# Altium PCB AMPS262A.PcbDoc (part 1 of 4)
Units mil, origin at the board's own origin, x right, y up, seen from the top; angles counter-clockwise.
Board outline 5314.96 x 4803.15 mil, 4 copper layers (Top Layer, GND, Copper Layer 3, Bottom Layer), stack 79.28 mil thick; 324 components, 156 nets, 943 pads, 1411 vias.
Unrouted connection lines stored in the file: 130.
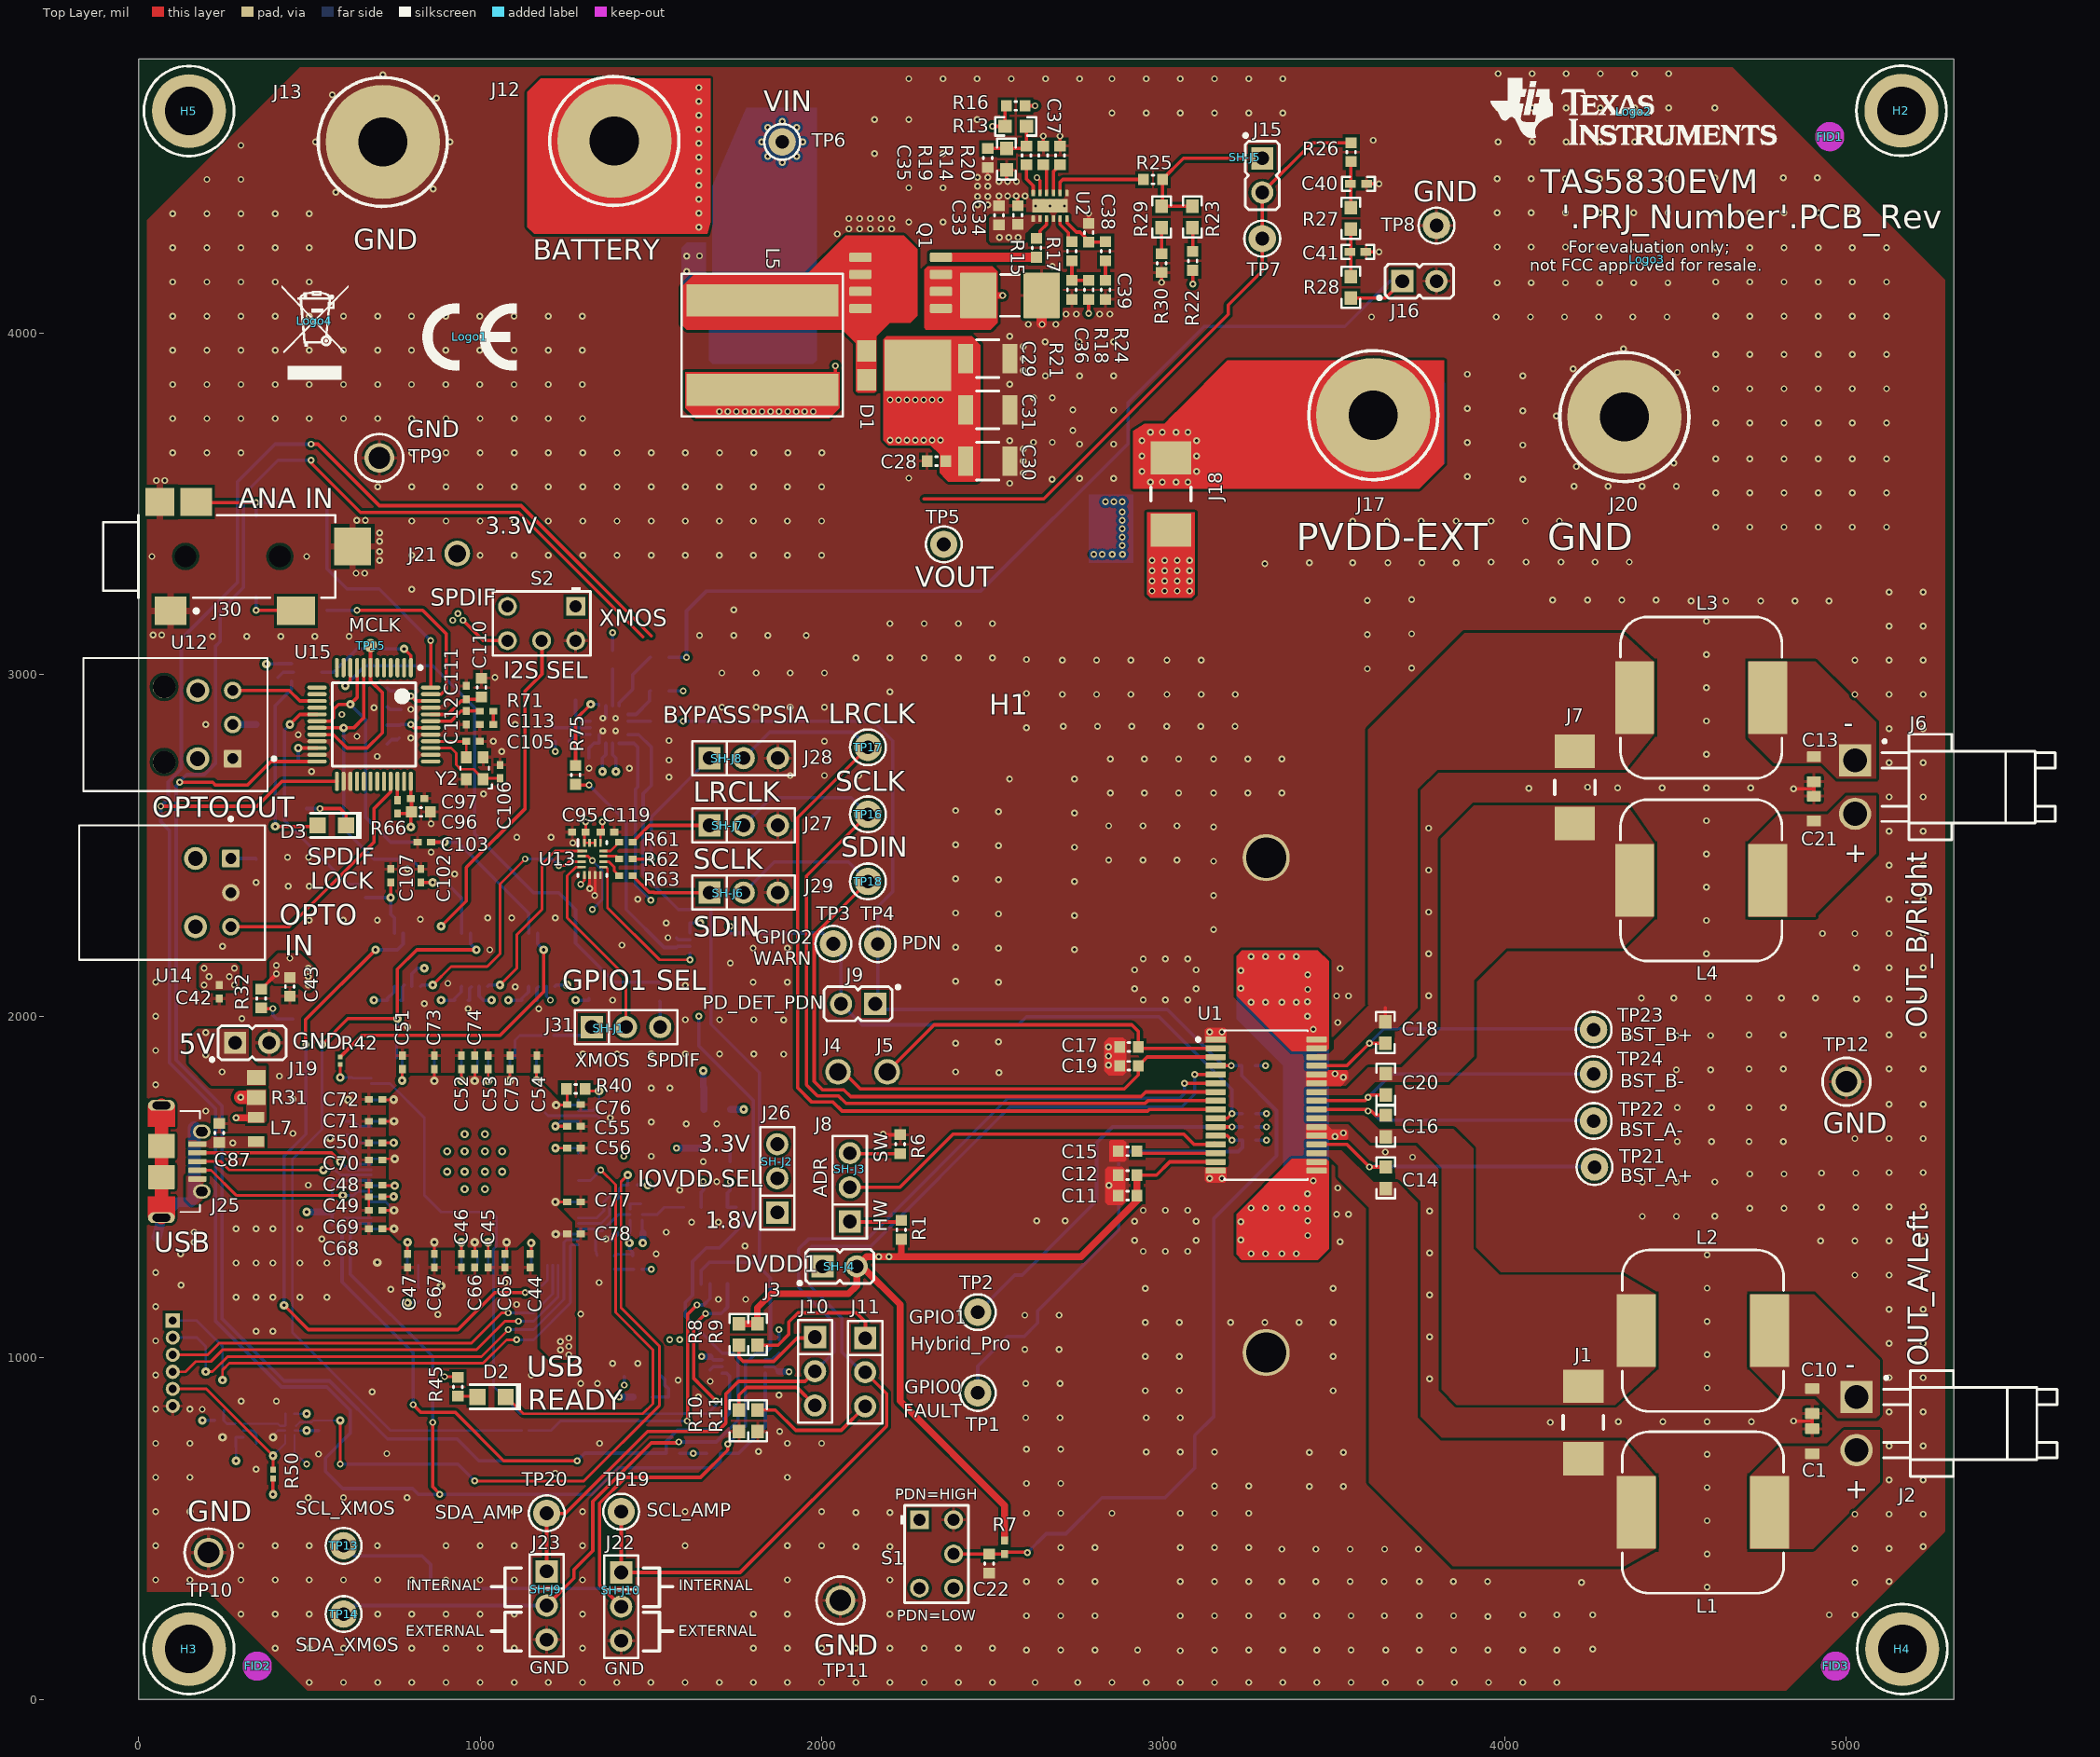
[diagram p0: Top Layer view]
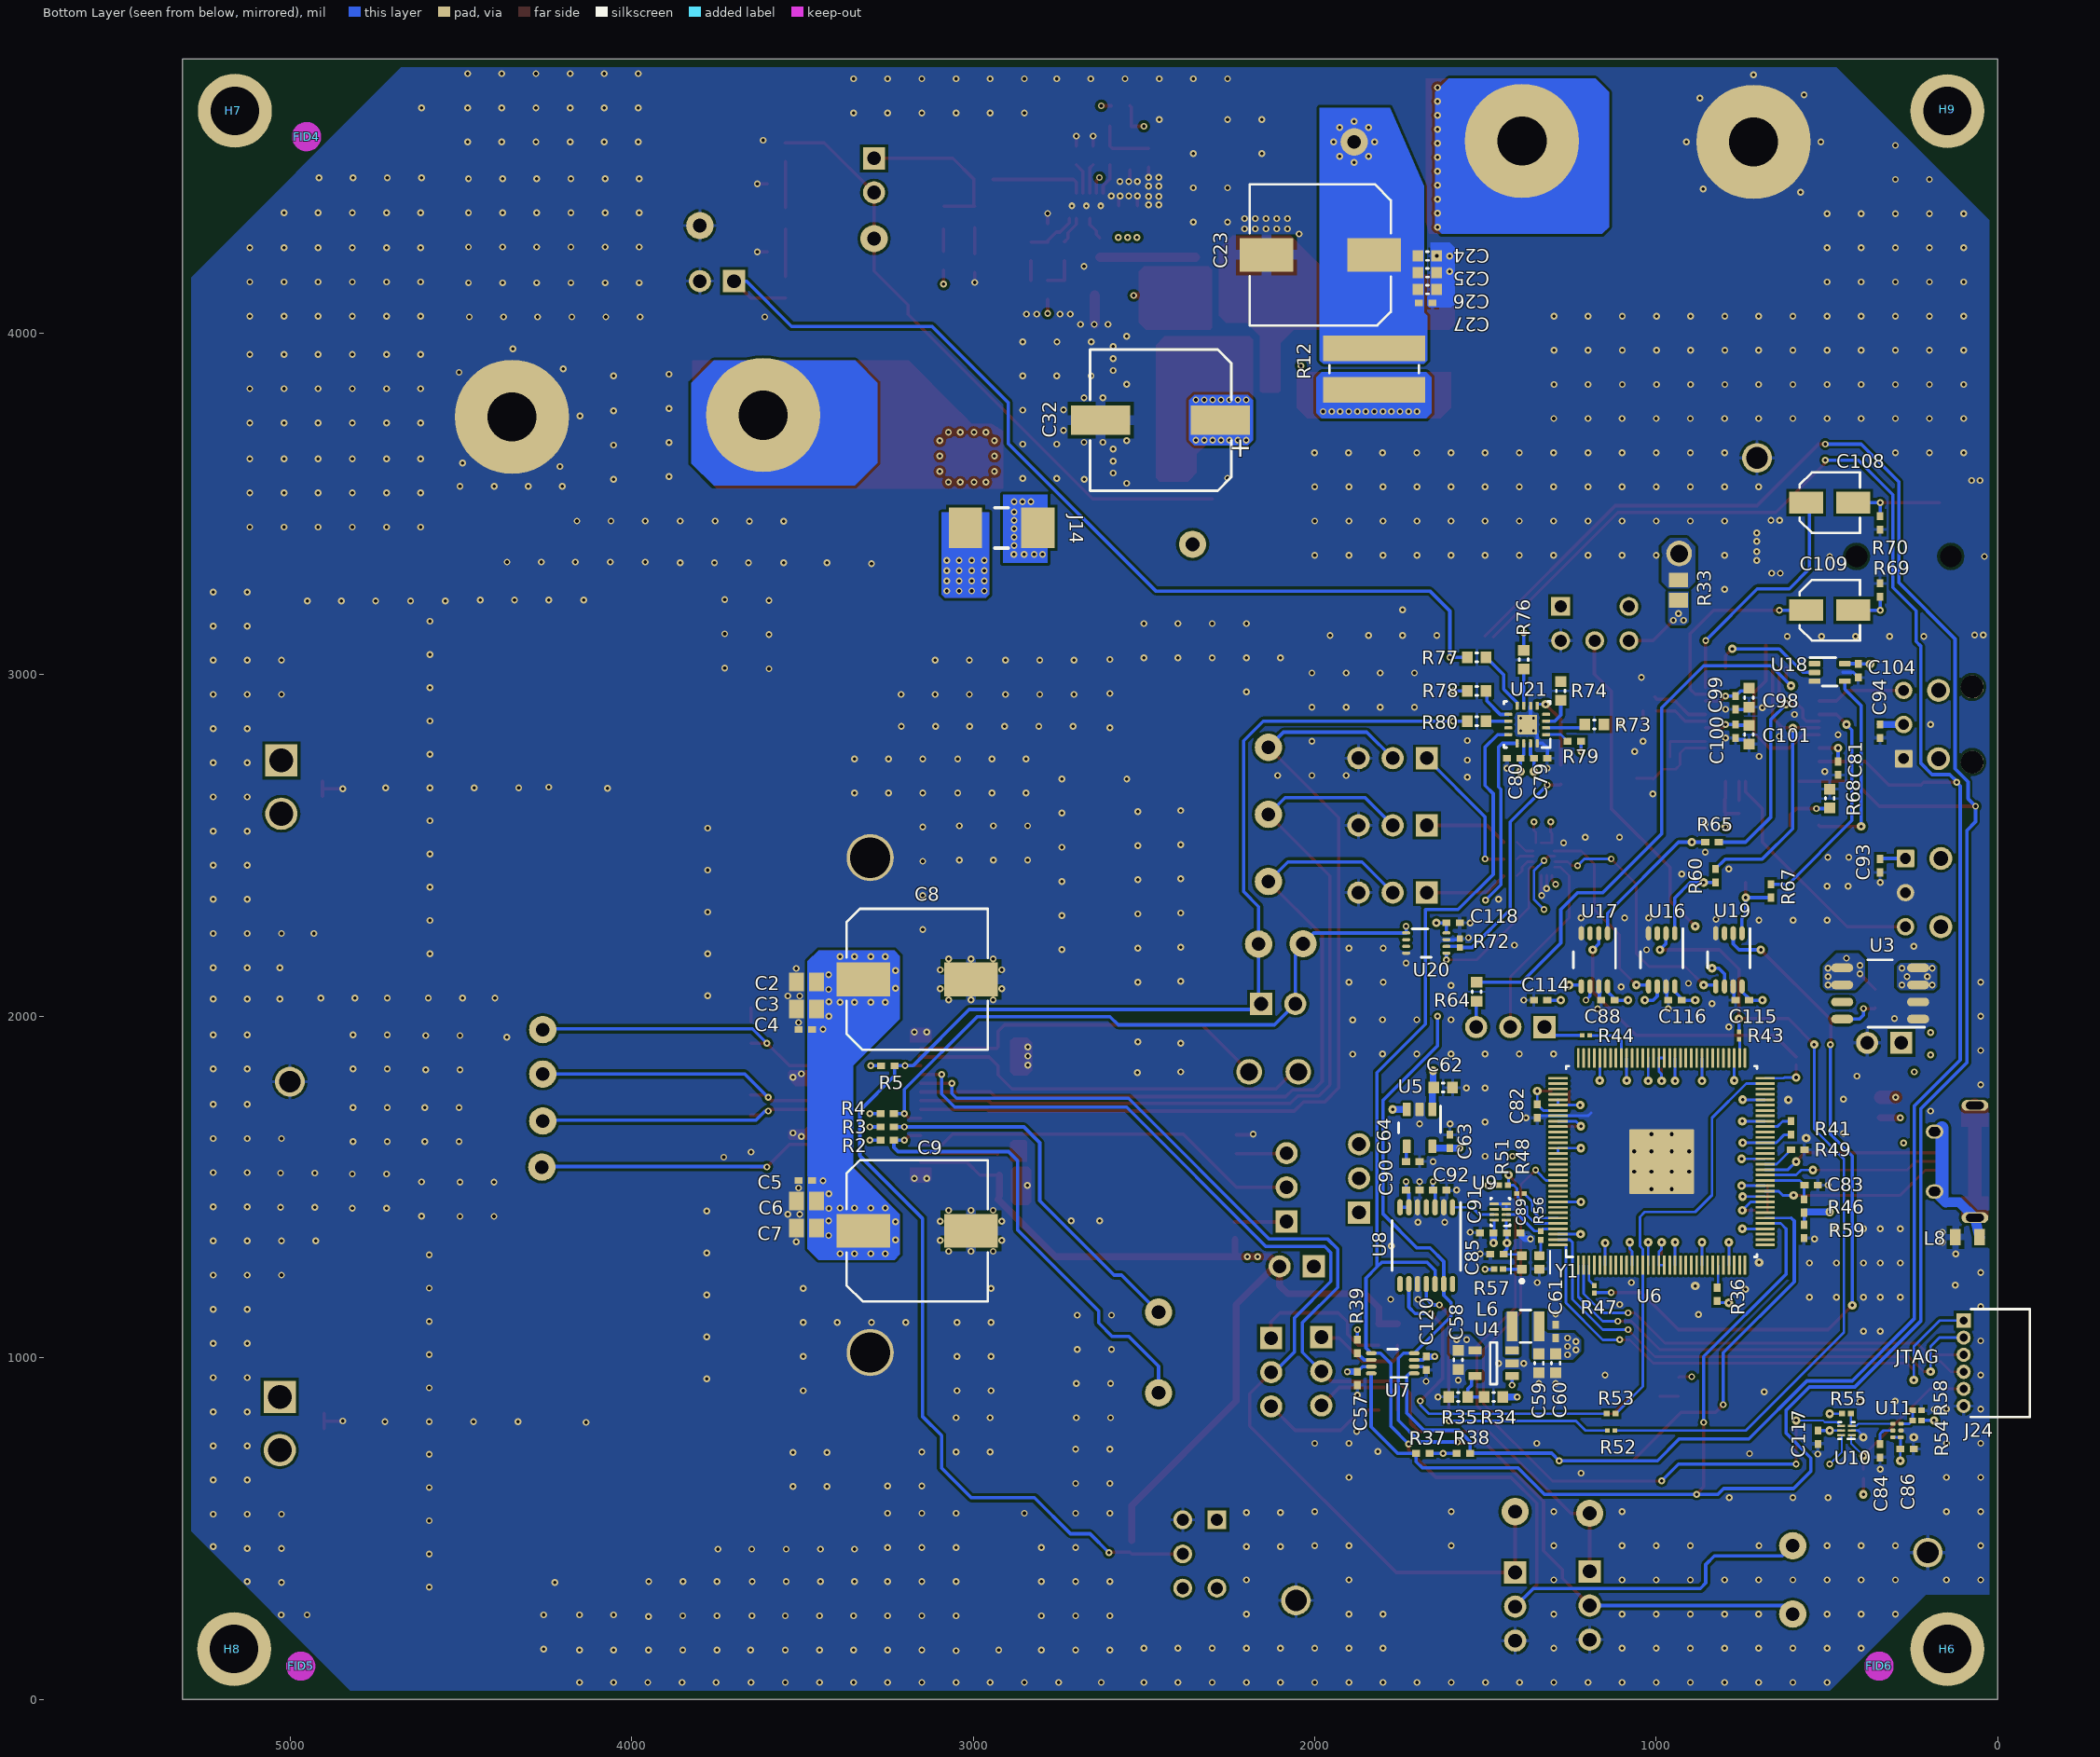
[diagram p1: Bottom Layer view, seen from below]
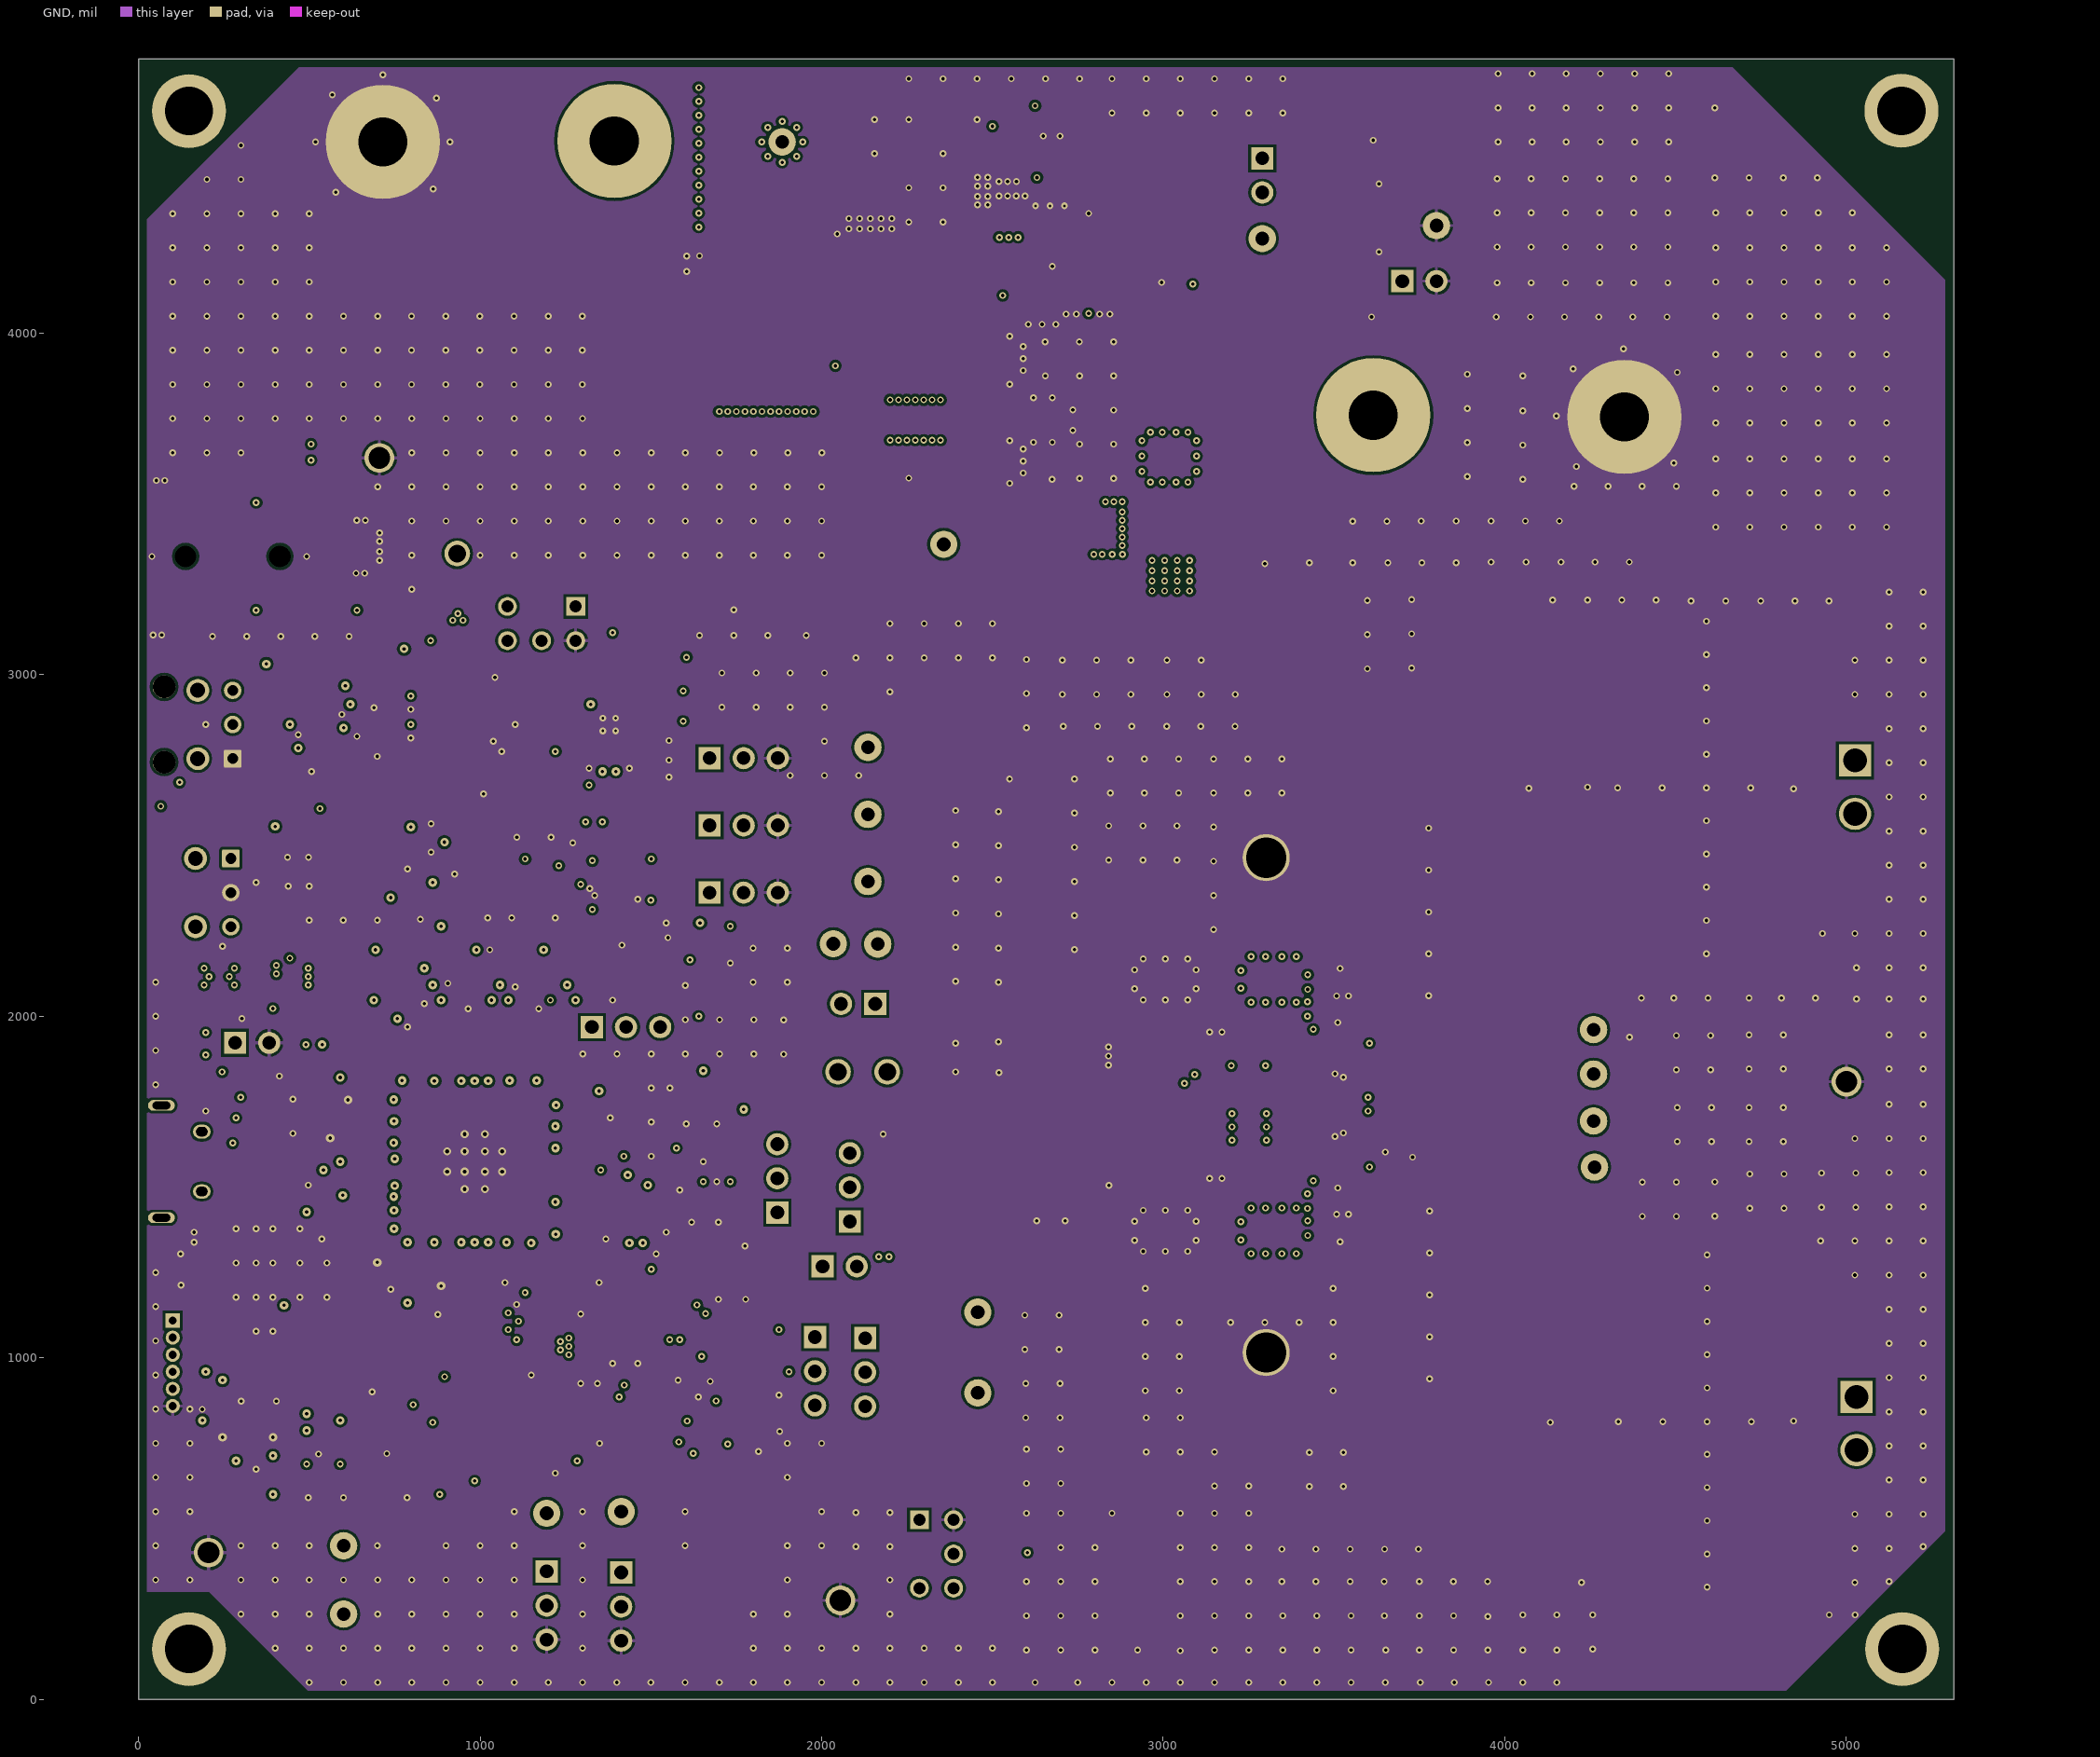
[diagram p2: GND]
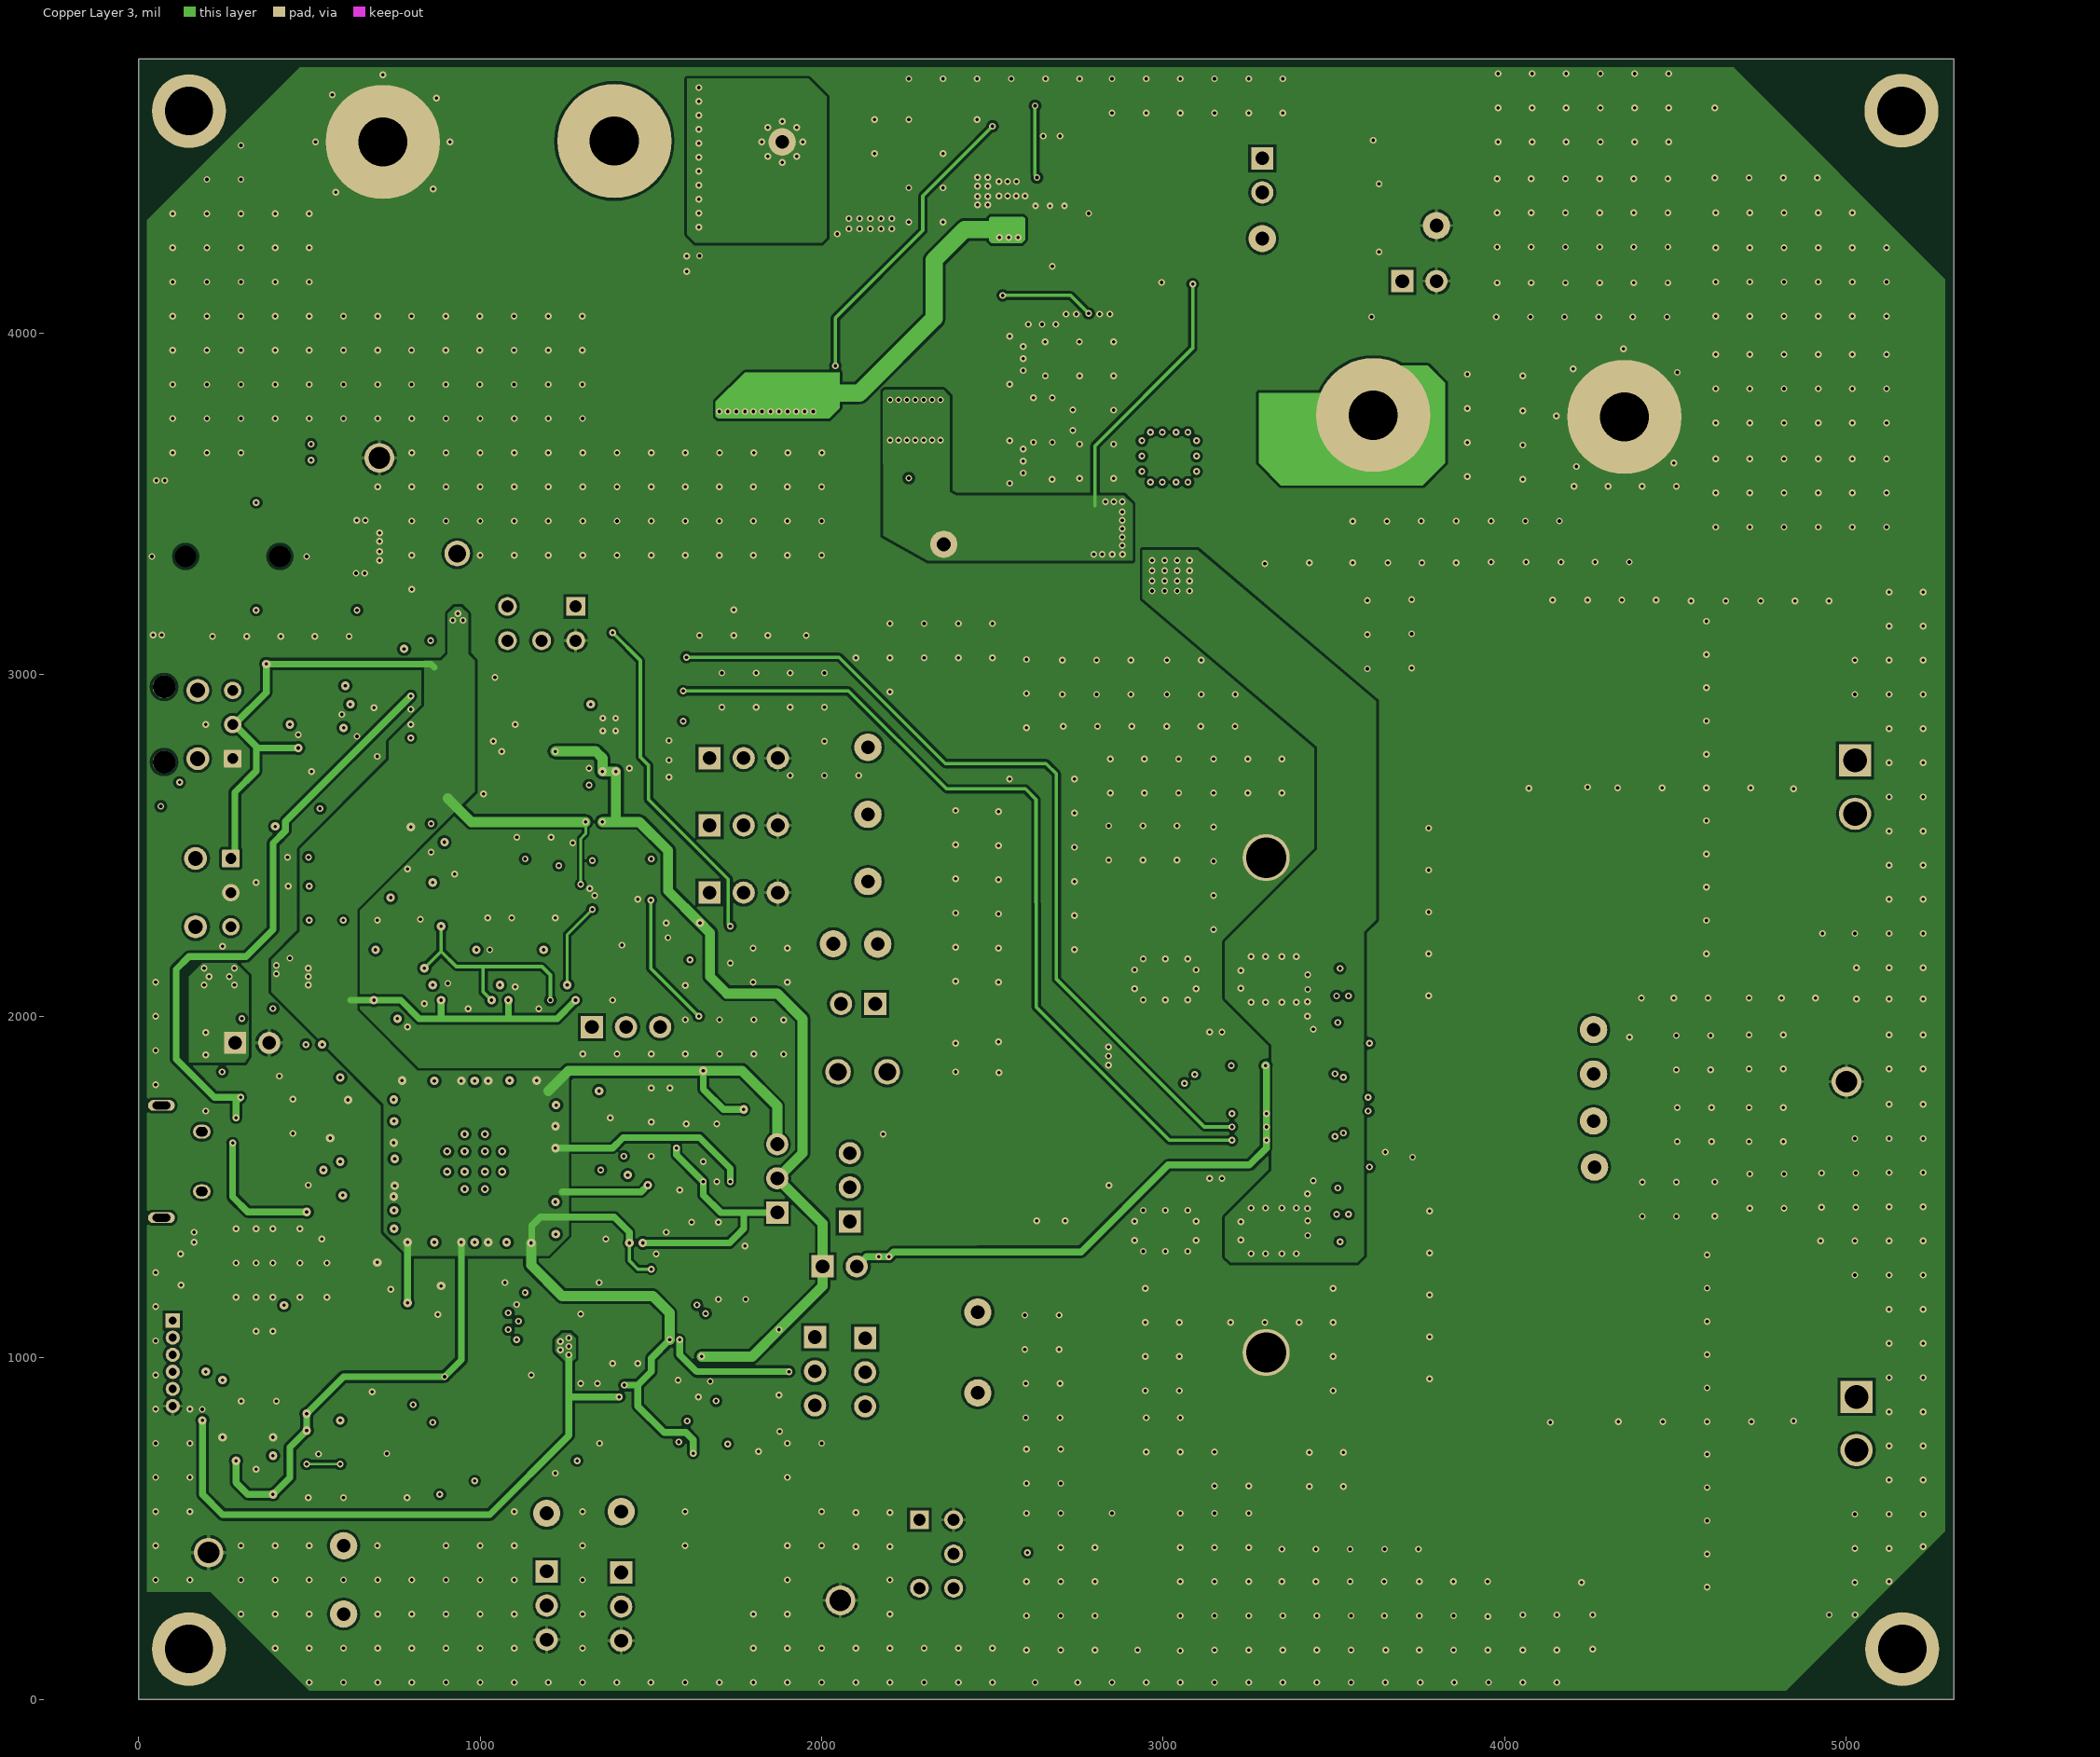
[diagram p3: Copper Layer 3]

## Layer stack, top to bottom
Top Solder: solder mask 0.4, Solder Resist, Dk 3.5
Top Layer: signal copper 2.74
Dielectric 1: prepreg 25, FR-4, Dk 4.2
GND: signal copper 1.4
Dielectric1: core 21, FR-4, Dk 4.2
Copper Layer 3: signal copper 1.4
Dielectric 3: prepreg 25, FR-4, Dk 4.2
Bottom Layer: signal copper 2.74
Bottom Solder: solder mask 0.4, Solder Resist, Dk 3.5

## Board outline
0,0 0,4803.15 5314.96,4803.15 5314.96,0

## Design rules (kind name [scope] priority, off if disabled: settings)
AcuteAngle [All] p1: minimum=4.50000000000000E+0001 checktracksonly=FALSE
AssemblyTestPointUsage [All] p1: valid=2
BoardOutlineClearance BoardOutlineClearance_MountingHoles [OnCopper and InComponentClass('Mounting Holes')] p1: gap=39.37 ignorepadtopadclearanceinfootprint=FALSE
BoardOutlineClearance BoardOutlineClearance_Poly [OnCopper and IsPoly] p2: gap=25 ignorepadtopadclearanceinfootprint=FALSE
BoardOutlineClearance BoardOutlineClearance_CONN_USB_DX4R205JJA [(OnCopper AND (HasFootprint('CONN_USB_DX4R205JJA') OR HasFootprint('SWITCHCRAFT_35RASM'))) and Not InComponentClass('Logo') and not InComponentClass('FiducialMark') and not InRegion(1000,500,4000,800) and not InPoly] p3: gap=75 ignorepadtopadclearanceinfootprint=FALSE except(15: SMDPad-OutlineEdge THPad-OutlineEdge; 29: Via-OutlineEdge)
BoardOutlineClearance [OnCopper and Not InComponentClass('Logo') and not InComponentClass('FiducialMark') and not InRegion(1000,500,4000,800) and not InPoly] p4: gap=75 ignorepadtopadclearanceinfootprint=FALSE except(20: Track-OutlineEdge; 25: Poly-OutlineEdge Poly-CavityEdge Poly-CutoutEdge Poly-SplitBarrior Poly-SplitContinuation Region-OutlineEdge Region-CavityEdge Region-CutoutEdge Region-SplitBarrior Region-SplitContinuation; 29: Via-OutlineEdge; 35: SMDPad-OutlineEdge; 39.37: THPad-OutlineEdge)
Clearance Clearance_FiducialMark [IsKeepOut and InComponentClass('FiducialMark') vs IsPad and InComponentClass('FiducialMark')] p1: gap=0 ignorepadtopadclearanceinfootprint=FALSE
Clearance Clearance_Keepouts [((IsTrack Or IsArc) And Not InPoly) And IsFree and IsKeepOut vs ((IsTrack Or IsArc) And Not InPoly) And IsFree and IsKeepOut] p2: gap=0 ignorepadtopadclearanceinfootprint=FALSE
Clearance Clearance_Poly [InPolygon] p3: gap=7.87 ignorepadtopadclearanceinfootprint=TRUE
Clearance "FootPrint Lib Error" [HasFootprint('DSF*')] p4: gap=7 ignorepadtopadclearanceinfootprint=TRUE except(0: Arc-Hole Track-Hole SMDPad-Hole THPad-Hole Via-Hole Fill-Hole Poly-Hole Region-Hole Text-Hole)
Clearance [All] p5: gap=7.87 ignorepadtopadclearanceinfootprint=TRUE except(0: Arc-Hole Track-Hole SMDPad-Hole THPad-Hole Via-Hole Fill-Hole Poly-Hole Region-Hole Text-Hole)
ComponentClearance ComponentClearance_MOUNTINGHOLE [HasFootprint('APM_RM3X8MM 2701') vs HasFootprint('Keystone_24434')] p1 off: gap=0 collisioncheckmode=3 verticalgap=0 showdistances=FALSE
ComponentClearance ComponentClearance_HEATSINK [InComponent('H1') vs InComponent('U1')] p2 off: gap=0 collisioncheckmode=3 verticalgap=0 showdistances=FALSE
ComponentClearance ComponentClearance_MountingHoles_FiducialMarks [InComponentClass('Mounting Holes') vs InComponentClass('FiducialMark')] p3 off: gap=50 collisioncheckmode=3 verticalgap=10 showdistances=FALSE
ComponentClearance ComponentClearance_Shunt [InComponentClass('Header') vs InComponentClass('Shunt')] p4 off: gap=0 collisioncheckmode=3 verticalgap=0 showdistances=FALSE
ComponentClearance ComponentClearance_Logo [InComponentClass('Logo')] p5 off: gap=50 collisioncheckmode=3 verticalgap=10 showdistances=FALSE
ComponentClearance ComponentClearance_ScrewToNut [(HasFootprint('NY PMS 440 0025 PH')) vs (HasFootprint('Keystone_1902C'))] p6 off: gap=5 collisioncheckmode=3 verticalgap=10 showdistances=FALSE
ComponentClearance ComponentClearance_MountingHoles [InComponentClass('Mounting Holes')] p7 off: gap=250 collisioncheckmode=3 verticalgap=100000 showdistances=FALSE
ComponentClearance ComponentClearance_SmallPassives [HasFootprint('0201*') or HasFootprint('0402*') or HasFootprint('0603*') or HasFootprint('0805*') or HasFootprint('1206*') or HasFootprint('1210*') or HasFootprint('1008*') or HasFootprint('2512*') or HasFootprint('Abracon*') or HasFootprint('DBV*') or HasFootprint('DC*') or HasFootprint('DDA*') or HasFootprint('DEM*') or HasFootprint('DFE*') or HasFootprint('DQM*') or HasFootprint('DRL*') or HasFootprint('DRY*') or HasFootprint('DSF*') or HasFootprint('DSS*') or HasFootprint('FDSD*') or HasFootprint('HAR*') or HasFootprint('HXB*') or HasFootprint('IND*') or HasFootprint('LDC*') or HasFootprint('LTST*') or HasFootprint('MPZ*') or HasFootprint('MRA*') or HasFootprint('NFZ*') or HasFootprint('PG*') or HasFootprint('PW*') or HasFootprint('PT*') or HasFootprint('Relay*') or HasFootprint('RGT*') or HasFootprint('RHB*') or HasFootprint('RLT*') or HasFootprint('RSV*') or HasFootprint('SM*') or HasFootprint('SOT*') or HasFootprint('TP*') or HasFootprint('VLS*') or HasFootprint('XAL*') or HasFootprint('XTAL*') vs HasFootprint('0201*') or HasFootprint('0402*') or HasFootprint('0603*') or HasFootprint('0805*') or HasFootprint('1206*') or HasFootprint('1210*') or HasFootprint('1008*') or HasFootprint('2512*') or HasFootprint('Abracon*') or HasFootprint('DBV*') or HasFootprint('DC*') or HasFootprint('DDA*') or HasFootprint('DEM*') or HasFootprint('DFE*') or HasFootprint('DQM*') or HasFootprint('DRL*') or HasFootprint('DRY*') or HasFootprint('DSF*') or HasFootprint('DSS*') or HasFootprint('FDSD*') or HasFootprint('HAR*') or HasFootprint('HXB*') or HasFootprint('IND*') or HasFootprint('LDC*') or HasFootprint('LTST*') or HasFootprint('MPZ*') or HasFootprint('MRA*') or HasFootprint('NFZ*') or HasFootprint('PG*') or HasFootprint('PW*') or HasFootprint('PT*') or HasFootprint('Relay*') or HasFootprint('RGT*') or HasFootprint('RHB*') or HasFootprint('RLT*') or HasFootprint('RSV*') or HasFootprint('SM*') or HasFootprint('SOT*') or HasFootprint('TP*') or HasFootprint('VLS*') or HasFootprint('XAL*') or HasFootprint('XTAL*')] p8 off: gap=8.5 collisioncheckmode=3 verticalgap=10 showdistances=FALSE
ComponentClearance ComponentClearance_THtoSMT [IsThruComponent vs IsSMTComponent] p9 off: gap=25 collisioncheckmode=3 verticalgap=30 showdistances=FALSE
ComponentClearance ComponentClearance_THtoTH [IsThruComponent vs IsThruComponent] p10 off: gap=30 collisioncheckmode=3 verticalgap=30 showdistances=FALSE
ComponentClearance [All] p11 off: gap=0 collisioncheckmode=3 verticalgap=10 showdistances=FALSE
DiffPairsRouting [All] p1: maxlimit=100 minlimit=10 mostfreqgap=10 toplayer_minwidth=15 toplayer_maxwidth=15 toplayer_prefwidth=15 midlayer1_minwidth=15 midlayer1_maxwidth=15 midlayer1_prefwidth=15 midlayer2_minwidth=15 midlayer2_maxwidth=15 midlayer2_prefwidth=15 bottomlayer_minwidth=15 bottomlayer_maxwidth=15 bottomlayer_prefwidth=15 maxuncoupledlength=1000
FabricationTestPointUsage TestPointUsage [All] p1: valid=2 allowmultiple=FALSE
FabricationTestpoint Testpoint [All] p1: side=3 testpointundercomponent=TRUE minsize=40 maxsize=100 preferedsize=60 minholesize=0 maxholesize=40 preferedholesize=32 testpointgrid=1 allowsidetop=TRUE allowsidebottom=TRUE usegrid=TRUE gridtolerance=0.01
FanoutControl Fanout_LCC [IsLCC] p1: bgadir=Out bgaviamode=Centered fanoutstyle=Auto fanoutdirection=Alternating viagrid=1 // Fanout_LCC (Default Rule)
FanoutControl Fanout_BGA [IsBGA] p2: bgadir=Out bgaviamode=Centered fanoutstyle=Auto fanoutdirection=Alternating viagrid=1 // Fanout_BGA (Default Rule)
FanoutControl Fanout_Default [All] p4: bgadir=Out bgaviamode=Centered fanoutstyle=Auto fanoutdirection=Alternating viagrid=1 // Fanout_Default (Default Rule)
FanoutControl Fanout_Small [(CompPinCount < 5)] p5: bgadir=Out bgaviamode=Centered fanoutstyle=Auto fanoutdirection=OutThenIn viagrid=1 // Fanout_Small (Default Rule)
Height [All] p1 off: minheight=0 maxheight=1050 prefheight=500
HoleSize [All] p1: absolutevalues=TRUE maxlimit=251 minlimit=7.87 maxpercent=80.000 minpercent=20.000
MinimumAnnularRing MinimumAnnularRing_ThermalPadVias [IsVia and InAnyComponent] p1: minimumring=5.91
MinimumAnnularRing [All] p2: minimumring=5
MinimumSolderMaskSliver MinimumSolderMaskSliver_Logo [InComponentClass('Logo') vs InComponentClass('Logo')] p1: minsoldermaskwidth=0.7
MinimumSolderMaskSliver MinimumSolderMaskSliver_DSF [HasFootprint('DSF*')] p2: minsoldermaskwidth=3.5
MinimumSolderMaskSliver [All] p3: minsoldermaskwidth=3.94
NetAntennae [InNet('No Net')] p1: netantennaetolerance=0
PlaneConnect [All] p1: planeconnectstyle=Relief reliefexpansion=10 reliefentries=4 reliefconductorwidth=10 reliefairgap=10
PolygonConnect "Flood VR Bottom Copper Only" [InNet('GND') vs HasFootprint('DDA0008H_N') And OnLayer('Bottom Copper')] p1: connectstyle=Direct reliefconductorwidth=10 reliefentries=4 polygonreliefangle="90 Angle" airgapwidth=10
PolygonConnect "Flood Copper Planes" [InNet('1.0V') or InNet('3.3V') or InNet('GND-PS') or InNet('PVDD') or  InNet('PVDD-VR') or  InNet('VIN') or InNet('3.3V-VR') or  InNet('VIN_3.3V-VR') or InNet('PVDD-3.3V')] p2: connectstyle=Direct reliefconductorwidth=10 reliefentries=4 polygonreliefangle="90 Angle" airgapwidth=10
PolygonConnect "Post Flood GND" [(HasFootprint('DKQ*') or HasFootprint('LDC*') or HasFootprint('MRA*') or HasFootprint('PW*') or HasFootprint('RHB*') or HasFootprint('RLT*') or HasFootprint('TQFP-128')) or InComponentClass('GND Thermals Full Flood') or InComponent('U*') or InComponentClass('GND Full Flood') vs InNet('GND')] p3: connectstyle=Direct reliefconductorwidth=10 reliefentries=4 polygonreliefangle="90 Angle" airgapwidth=10
PolygonConnect "GND Thermals 0.5mm" [InComponentClass('GND Thermals 0.5mm') vs InNet('GND')] p4: connectstyle=Relief reliefconductorwidth=19.68 reliefentries=4 polygonreliefangle="90 Angle" airgapwidth=9.84
PolygonConnect "PVDD Thermals 0.75mm" [InComponentClass('GND Thermals 0.75mm') vs InNet('GND')] p5: connectstyle=Relief reliefconductorwidth=29.53 reliefentries=4 polygonreliefangle="90 Angle" airgapwidth=9.84
PolygonConnect "GND Thermals 0.25mm" [InComponent('C*') or InComponent('J*') or InComponent('L*') or  InComponent('R*') or InComponent('S*') or InComponent('TP*') or  InComponent('Y*') or  InComponent('GND*') vs InNet('GND')] p6: connectstyle=Relief reliefconductorwidth=9.84 reliefentries=4 polygonreliefangle="90 Angle" airgapwidth=7.87
PolygonConnect "Pre Flood" [All] p7: connectstyle=Direct reliefconductorwidth=10 reliefentries=4 polygonreliefangle="90 Angle" airgapwidth=10
RoutingVias ThermalPadVias [IsVia and InAnyComponent] p1: holewidth=7.87 width=19.68 viastyle="Through Hole" minholewidth=7.87 minwidth=19.68 maxholewidth=12.99 maxwidth=23.62
RoutingVias [All] p2: holewidth=10 width=20 viastyle="Through Hole" minholewidth=7.87 minwidth=20 maxholewidth=40 maxwidth=65
SilkToBoardRegionClearance [Not ((IsComment or IsDesignator) And (Hide <> 'False')) and not InRegion(1000,500,4000,800)] p1:
SilkToSilkClearance SilkToSilkClearance_Pb-FreeLogo [(HasFootprint('Pb-Free_Overlay_Medium') OR HasFootprint('Pb-Free_Overlay_Small')) vs (HasFootprint('Pb-Free_Overlay_Medium') OR HasFootprint('Pb-Free_Overlay_Small'))] p1: silktosilkclearance=0
SilkToSilkClearance [All] p2: silktosilkclearance=3.94
SilkToSolderMaskClearance SilkToComponentPadClearance_LTST [HasFootprint('LTST*')] p1: minsilkscreentomaskgap=3.5 clearancetoexposedcopper=TRUE
SilkToSolderMaskClearance SilkToComponentPadClearance_DSF0006A [HasFootprint('DSF0006A') or HasFootprint('LTST-C170TBKT_Blue') vs (IsPad or IsFill or IsRegion)] p2: minsilkscreentomaskgap=3.5 clearancetoexposedcopper=TRUE
SilkToSolderMaskClearance SilkToComponentPadClearance_1008 [HasFootprint('1008') vs (IsPad or IsFill or IsRegion)] p3: minsilkscreentomaskgap=2.2 clearancetoexposedcopper=TRUE
SilkToSolderMaskClearance SilkToComponentPadClearance [(IsPad or IsFill or IsRegion) and InAnycomponent] p4: minsilkscreentomaskgap=5 clearancetoexposedcopper=TRUE
SilkToSolderMaskClearance "Silk to Solder Mask Opening" [All] p5: minsilkscreentomaskgap=3.94 clearancetoexposedcopper=FALSE
SolderMaskExpansion [All] p1: expansion=1.97 istentingtop=FALSE
UnRoutedNet [All] p1: checkbadconnections=TRUE
Width [All] p1: maxlimit=100 minlimit=6 preferedwidth=10 checkconnectedcopper=TRUE
12 further rules are at their usual default settings.

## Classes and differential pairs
component class Shunt: SH-J1 SH-J2 SH-J3 SH-J4 SH-J5 SH-J6 SH-J7 SH-J8 SH-J9 SH-J10
component class Header: J3 J8 J9 J10 J11 J15 J16 J19 J22 J23 J26 J27 J28 J29 J31
component class "GND Thermals Full Flood": C33 C35 C38 C58 C59 C60 U2
component class "GND Thermals 0.75mm": C8 C9 C23 C32
component class "GND Thermals 0.5mm": J30 L8
component class "GND Full Flood": C2 C3 C4 C5 C6 C7 C11 C12 C15 C17 C19 C22 C29 C30 C31 C61 J13 J20 U7
component class AMPS262A_USB: C44 C45 C46 C47 C48 C49 C50 C51 C52 C53 C54 C55 C56 C57 C58 C59 C60 C61 C62 C63 C64 C65 C66 C67 C68 C69 C70 C71 C72 C73 C74 C75 C76 C77 C78 C79 C80 C81 C82 C83 C84 C85 C86 C87 C88 C89 C90 C91 C92 D2 J22 J23 J24 J25 L6 L7 L8 R34 R35 R36 R37 R38 R39 R40 R41 R42 R43 R44 R45 R46 R47 R48 R49 R50 R51 R52 R53 R54 R55 R56 R57 R58 R59 TP13 TP14 TP19 TP20 U4 U5 U6 U7 U8 U9 U10 U11 Y1
component class AMPS262A_TAS5830_IO: C1 C2 C3 C4 C5 C6 C7 C8 C9 C10 C11 C12 C13 C14 C15 C16 C17 C18 C19 C20 C21 C22 H1 J1 J2 J3 J4 J5 J6 J7 J8 J9 J10 J11 L1 L2 L3 L4 R1 R2 R3 R4 R5 R6 R7 R8 R9 R10 R11 S1 TP1 TP2 TP3 TP4 TP21 TP22 TP23 TP24 U1
component class AMPS262A_SPDIF_I2S_PSIA: C93 C94 C95 C96 C97 C98 C99 C100 C101 C102 C103 C104 C105 C106 C107 C108 C109 C110 C111 C112 C113 C114 C115 C116 C117 C118 C119 C120 D3 J26 J27 J28 J29 J30 J31 R60 R61 R62 R63 R64 R65 R66 R67 R68 R69 R70 R71 R72 R73 R74 R75 R76 R77 R78 R79 R80 S2 TP15 TP16 TP17 TP18 U12 U13 U14 U15 U16 U17 U18 U19 U20 U21 Y2
component class AMPS262A_PowerSupplies: C23 C24 C25 C26 C27 C28 C29 C30 C31 C32 C33 C34 C35 C36 C37 C38 C39 C40 C41 C42 C43 D1 J12 J13 J14 J15 J16 J17 J18 J19 J20 J21 L5 Q1 R12 R13 R14 R15 R16 R17 R18 R19 R20 R21 R22 R23 R24 R25 R26 R27 R28 R29 R30 R31 R32 R33 TP5 TP6 TP7 TP8 TP9 TP10 TP11 TP12 U2 U3
component class Hardware: H2 H3 H4 H5 H6 H7 H8 H9
component class Logo: Logo2
component class AMPS262A_Hardware: FID1 FID2 FID3 FID4 FID5 FID6 H2 H3 H4 H5 H6 H7 H8 H9 Logo1 Logo2 Logo3 Logo4 SH-J1 SH-J2 SH-J3 SH-J4 SH-J5 SH-J6 SH-J7 SH-J8 SH-J9 SH-J10 ZZ1 ZZ2 ZZ3
component class FiducialMark: FID1 FID2 FID3 FID4 FID5 FID6
component class AssemblyNote: ZZ1 ZZ2 ZZ3

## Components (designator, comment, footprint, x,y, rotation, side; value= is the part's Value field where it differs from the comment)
C1 "CGA4J3X7R1H684M125AB" FP-CGA4J3X7R1H684M125AB_0805-MFG 4900,756.02 r270 top
C2 "C2012X5R1V106K085AC" 0805L 3488.08,2100.24 r180 bottom value=10uF
C3 "" 0805L 3487.54,2021.2 r180 bottom value=10uF
C4 "CGA2B3X7R1H104K050BB" 0402L 3490.98,1961.07 r0 bottom value=0.1uF
C5 "CGA2B3X7R1H104K050BB" 0402L 3490.98,1519.19 r0 bottom value=0.1uF
C6 "" 0805L 3487.54,1459.05 r180 bottom value=10uF
C7 "C2012X5R1V106K085AC" 0805L 3488.08,1380.02 r180 bottom value=10uF
C8 "+" SM_RADIAL_10BMM 3163.94,2108.19 r180 bottom value=390uF
C9 "+" SM_RADIAL_10BMM 3163.94,1372.07 r180 bottom value=390uF
C10 "CGA4J3X7R1H684M125AB" FP-CGA4J3X7R1H684M125AB_0805-MFG 4900,873.52 r90 top
C11 "Capacitor" 0603L 2895.72,1475 r0 top value=4.7uF
C12 "Capacitor" 0603L 2895.72,1535 r180 top value=0.1uF
C13 "CGA4J3X7R1H684M125AB" FP-CGA4J3X7R1H684M125AB_0805-MFG 4905,2723.52 r90 top
C14 "C1608X7R1H474K080AC" 0603 3651.25,1527.5 r270 top value=0.47uF
C15 "CL10B105MO8NNWC" 0603L 2895.72,1605 r180 top value=1uF
C16 "C1608X7R1H474K080AC" 0603 3651.28,1678.86 r270 top value=0.47uF
C17 "CL10B105MO8NNWC" 0603L 2899.66,1910 r180 top value=1uF
C18 "C1608X7R1H474K080AC" 0603 3650,1952.5 r90 top value=0.47uF
C19 "CL10B105MO8NNWC" 0603L 2899.66,1855.24 r180 top value=1uF
C20 "C1608X7R1H474K080AC" 0603 3651.28,1801.39 r90 top value=0.47uF
C21 "CGA4J3X7R1H684M125AB" FP-CGA4J3X7R1H684M125AB_0805-MFG 4905,2608.52 r270 top
C22 "Capacitor" 0603L 2490.5,397.94 r270 top value=0.1uF
C23 "+" SM_RADIAL_10BMM 1983.79,4229.51 r0 bottom value=100uF
C24 "GRM188R61E106KA73D" 0603L 1670.17,4226.28 r180 bottom value=10uF
C25 "GRM188R61E106KA73D" 0603L 1670.17,4177.07 r180 bottom value=10uF
C26 "GRM188R61E106KA73D" 0603L 1670.17,4127.86 r180 bottom value=10uF
C27 "CGA2B3X7R1E104K050BB" 0402L 1675.09,4088.49 r180 bottom value=0.1uF
C28 "CGA3E2X7R1H104K080AA" 0603L 2336.31,3625.65 r180 top value=0.1uF
C29 "CGA6P3X7R1H475K250AB" 1210_280 2486.31,3925.65 r0 top value=4.7uF
C30 "CGA6P3X7R1H475K250AB" 1210_280 2486.31,3625.65 r0 top value=4.7uF
C31 "CGA6P3X7R1H475K250AB" 1210_280 2486.31,3775.65 r0 top value=4.7uF
C32 "+" HXB_JA0 2451.31,3745.65 r0 bottom value=100uF
C33 "GCM188R71C105MA64D" 0603L 2519.11,4345.09 r270 top value=1uF
C34 "GCM188R71H103KA37D" 0603L 2574.11,4345.65 r90 top value=0.01uF
C35 "DNP" 0603L 2486.31,4513.09 r270 top value=100pF
C36 "C0603C101F5GACTU" 0603L 2732.53,4126.83 r270 top value=100pF
C37 "CGA3E3X7R1H224K080AB" 0603L 2698.08,4520.53 r270 top value=0.22uF
C38 "CGA3E2C0G1H221J080AA" 0603L 2781.75,4294.16 r90 top value=220pF
C39 "C0603C223K4RACTU" 0603L 2830.96,4240.02 r270 top value=0.022uF
C40 "CGA2B2C0G1H221J050BA" 0402 3571.5,4437.61 r0 top value=220pF
C41 "CGA2B2C0G1H221J050BA" 0402 3569.5,4237.61 r0 top value=220pF
C42 "885012205037" 0402L 236.22,2071.85 r90 top value=0.1uF
C43 "Capacitor" 0603L 442.91,2086.61 r270 top value=10uF
C44 "885012205037" 0402L 1146.65,1284.45 r90 top value=0.1uF
C45 "885012205037" 0402L 1023.62,1284.45 r90 top value=0.1uF
C46 "885012205037" 0402L 944.88,1284.45 r90 top value=0.1uF
C47 "885012205037" 0402L 787.4,1284.45 r90 top value=0.1uF
C48 "885012205037" 0402L 693.9,1505.91 r0 top value=0.1uF
C49 "885012205037" 0402L 693.9,1471.46 r0 top value=0.1uF
C50 "885012205037" 0402L 693.9,1628.94 r0 top value=0.1uF
C51 "885012205037" 0402L 772.64,1865.16 r270 top value=0.1uF
C52 "885012205037" 0402L 944.88,1865.16 r270 top value=0.1uF
C53 "885012205037" 0402L 1023.62,1865.16 r270 top value=0.1uF
C54 "885012205037" 0402L 1166.34,1865.16 r270 top value=0.1uF
C55 "885012205037" 0402L 1274.61,1678.15 r180 top value=0.1uF
C56 "885012205037" 0402L 1274.61,1614.17 r180 top value=0.1uF
C57 "885012205037" 0402L 1875,939.96 r90 bottom value=0.1uF
C58 "C1608X5R1A226M080AC" 0603L 1579.72,994.09 r270 bottom value=22uF
C59 "C1608X5R1A226M080AC" 0603L 1343.5,984.25 r270 bottom value=22uF
C60 "C1608X5R1A226M080AC" 0603L 1294.29,984.25 r270 bottom value=22uF
C61 "885012205037" 0402L 1294.29,1077.76 r90 bottom value=0.1uF
C62 "C1608X5R1A106M080AC" 0603L 1624.02,1791.34 r180 bottom value=10uF
C63 "GRM152R60J105ME15D" 0402L 1604.33,1633.86 r270 bottom value=1uF
C64 "885012205031" 0402L 1712.6,1574.8 r0 bottom value=0.01uF
C65 "885012205037" 0402L 1072.83,1284.45 r90 top value=0.1uF
C66 "885012205037" 0402L 984.25,1284.45 r90 top value=0.1uF
C67 "885012205037" 0402L 866.14,1284.45 r90 top value=0.1uF
C68 "885012205037" 0402L 693.9,1377.95 r0 top value=0.1uF
C69 "885012205037" 0402L 693.9,1432.09 r0 top value=0.1uF
C70 "885012205037" 0402L 693.9,1579.72 r0 top value=0.1uF
C71 "885012205037" 0402L 693.9,1692.91 r0 top value=0.1uF
C72 "885012205037" 0402L 693.9,1756.89 r0 top value=0.1uF
C73 "885012205037" 0402L 866.14,1865.16 r270 top value=0.1uF
C74 "885012205037" 0402L 984.25,1865.16 r270 top value=0.1uF
C75 "885012205037" 0402L 1087.6,1865.16 r270 top value=0.1uF
C76 "885012205037" 0402L 1274.61,1742.13 r180 top value=0.1uF
C77 "885012205037" 0402L 1274.61,1456.69 r180 top value=0.1uF
C78 "885012205037" 0402L 1274.61,1363.19 r180 top value=0.1uF
C79 "885012205037" 0402L 1338.58,2755.91 r0 bottom value=0.1uF
C80 "885012205037" 0402L 1417.32,2755.91 r180 bottom value=0.1uF
C81 "885012205037" 0402L 467.52,2726.38 r90 bottom value=0.1uF
C82 "885012205037" 0402L 1348.43,1722.44 r270 bottom value=0.1uF
C83 "885012205037" 0402L 546.26,1505.91 r180 bottom value=0.1uF
C84 "GRM1555C1H471JA01D" 0402L 344.49,728.35 r90 bottom value=470pF
C85 "885012205037" 0402L 1466.54,1304.13 r180 bottom value=0.1uF
C86 "885012205037" 0402L 265.75,733.27 r0 bottom value=0.1uF
C87 "Capacitor" 0603L 236.38,1658.46 r270 top value=2.2uF
C88 "885012205037" 0402L 1141.73,2047.24 r180 bottom value=0.1uF
C89 "885012205037" 0402L 1417.32,1366.14 r0 bottom value=0.1uF
C90 "885012205037" 0402L 1712.6,1491.14 r0 bottom value=0.1uF
C91 "885012205037" 0402L 1496.06,1366.14 r180 bottom value=0.1uF
C92 "885012205037" 0402L 1633.86,1491.14 r0 bottom value=0.1uF
C93 "885012205037" 0402L 344.49,2440.94 r270 bottom value=0.1uF
C94 "885012205037" 0402L 344.49,2834.65 r270 bottom value=0.1uF
C95 "885012205037" 0402L 1289.37,2539.37 r180 top value=0.1uF
C96 "EMK107BBJ106MA-T" 0603L 826.77,2598.43 r0 top value=10uF
C97 "885012205037" 0402L 816.93,2637.8 r0 top value=0.1uF
C98 "EMK107BBJ106MA-T" 0603L 728.35,2933.07 r270 bottom value=10uF
C99 "885012205037" 0402L 767.72,2918.31 r270 bottom value=0.1uF
C100 "885012205037" 0402L 767.72,2834.65 r270 bottom value=0.1uF
C101 "EMK107BBJ106MA-T" 0603L 728.35,2824.8 r270 bottom value=10uF
C102 "885012005055" 0402L 826.77,2411.42 r90 top value=10pF
C103 "885012005055" 0402L 836.61,2509.84 r180 top value=10pF
C104 "885012205037" 0402L 408.46,3011.81 r270 bottom value=0.1uF
C105 "GJM1555C1H270JB01" 0402L 979.33,2805.12 r0 top value=27pF
C106 "GJM1555C1H270JB01" 0402L 1058.07,2716.54 r90 top value=27pF
C107 "885012005055" 0402L 738.19,2411.42 r90 top value=10pF
C108 "EEE-FC1C100R" SM_RADIAL_B 492.13,3503.94 r180 bottom value=10uF
C109 "EEE-FC1C100R" SM_RADIAL_B 492.13,3188.98 r180 bottom value=10uF
C110 "EMK107BBJ106MA-T" 0603L 1003.94,2962.6 r90 top value=10uF
C111 "885012205037" 0402L 959.65,2947.83 r90 top value=0.1uF
C112 "CC0402KRX7R8BB472" 0402L 959.65,2874.02 r270 top value=4700pF
C113 "CGA2B3X7R1H683K050BB" 0402L 1018.7,2854.33 r180 top value=0.068uF
C114 "885012205037" 0402L 1338.58,2047.24 r0 bottom value=0.1uF
C115 "885012205037" 0402L 748.03,2047.24 r0 bottom value=0.1uF
C116 "885012205037" 0402L 944.88,2047.24 r0 bottom value=0.1uF
C117 "885012205037" 0402L 526.57,767.72 r270 bottom value=0.1uF
C118 "885012205037" 0402L 1594.49,2273.62 r180 bottom value=0.1uF
C119 "885012205037" 0402L 1373.03,2539.37 r0 top value=0.1uF
C120 "885012205037" 0402L 1673.23,984.25 r270 bottom value=0.1uF
D1 "PMEG060V100EPDZ" SOT1289 2241.16,3905.65 r90 top value=60V
D2 "USB RDY" LTST-C170TBKT_Blue 1033.46,885.83 r0 top value=Blue
D3 "S/PDIF LOCK" LTST-C170TBKT_Blue 565.94,2559.06 r0 top value=Blue
FID1 "DNP" Fiducial6.4-20 4951.22,4575.51 r0 top
FID2 "DNP" Fiducial6.4-20 347.64,97.64 r0 top
FID3 "DNP" Fiducial6.4-20 4968.72,97.64 r0 top
FID4 "DNP" Fiducial6.4-20 4951.22,4575.51 r180 bottom
FID5 "DNP" Fiducial6.4-20 4968.72,97.64 r180 bottom
FID6 "DNP" Fiducial6.4-20 347.64,97.64 r180 bottom
H1 "ATS-TI1OP-519-C1-R3" HSINK_ATS078036036-TI1OP-519-C1-R3 3301.36,1740.13 r90 top
H2 "M3x8mm" "APM_RM3X8MM 2701" 5161.22,4651.02 r0 top
H3 "M3x8mm" "APM_RM3X8MM 2701" 147.64,147.64 r0 top
H4 "M3x8mm" "APM_RM3X8MM 2701" 5163.72,147.64 r0 top
H5 "M3x8mm" "APM_RM3X8MM 2701" 147.64,4650.51 r0 top
H6 "M3x12mm" Keystone_24434 147.64,147.64 r180 bottom
H7 "M3x12mm" Keystone_24434 5166.22,4651.02 r180 bottom
H8 "M3x12mm" Keystone_24434 5168.72,147.64 r180 bottom
H9 "M3x12mm" Keystone_24434 147.64,4655.51 r180 bottom
J1 "DNP" HARWIN_S1911-46R 4230,811.02 r270 top
J2 "Left" JST_B2PS-VH 5030,807.95 r0 top
J3 "DVDD1" Sullins_PBC02SAAN 2052.69,1267.97 r90 top
J4 "GVDD" CONN_1040 2047.86,1837.54 r0 top
J5 "AVDD" CONN_1040 2191.86,1837.54 r0 top
J6 "Right" JST_B2PS-VH 5025.38,2671.02 r0 top
J7 "DNP" HARWIN_S1911-46R 4205,2670.16 r90 top
J8 "ADR/HW" PBC03SAAN 2082.31,1499.37 r90 top
J9 "PD_DET-PDN" Sullins_PBC02SAAN 2106.62,2036.56 r270 top
J10 "SDA/HW_SEL0" PBC03SAAN 1980.41,960.95 r270 top
J11 "SCL/HW_SEL1" PBC03SAAN 2127.41,957.95 r270 top
J12 "Battery" Keystone_7006 1393.01,4562.74 r0 top locked
J13 "GND" Keystone_7007 715,4560 r0 top locked
J14 "DNP" HARWIN_S1911-46R 2916.44,3430 r0 bottom
J15 "Ext_BST" Sullins_PBC02SAAN 3290,4461.95 r0 top
J16 "BST_Bypass" Sullins_PBC02SAAN 3750,4152.5 r90 top
J17 "PVDD" Keystone_7006 3615,3760 r0 top
J18 "PVDD_EXT" HARWIN_S1911-46R 3022.5,3529.09 r270 top
J19 "5V" Sullins_PBC02SAAN 332.5,1922.5 r90 top
J20 "GND" Keystone_7007 4350,3754.71 r0 top
J21 "3.3V" CONN_1040 932.99,3354.88 r0 top
J22 "SCL" PBC03SAAN 1413,272 r270 top
J23 "SDA" PBC03SAAN 1195,275 r270 top
J24 "JTAG" SULLINS_LPPB061NGCN-RC 0,984.25 r90 bottom
J25 "USB" Molex_0475890001 10,1574.8 r270 top
J26 "IOVDD SEL" PBC03SAAN 1870.08,1525.59 r90 top
J27 "SCLK" PBC03SAAN 1771.65,2559.06 r0 top
J28 "LRCLK" PBC03SAAN 1771.65,2755.91 r0 top
J29 "SDIN" PBC03SAAN 1771.65,2362.2 r0 top
J30 "ANA IN" Switchcraft_35RASM 236.22,3346.46 r90 top locked
J31 "GPIO1 SEL" PBC03SAAN 1427.17,1968.5 r0 top
L1 "7447709100" WE-PD_1210 4580,547.36 r0 top value=10uH
L2 "7447709100" WE-PD_1210 4580,1079.65 r0 top value=10uH
L3 "7447709100" WE-PD_1210 4575,2933.03 r0 top value=10uH
L4 "7447709100" WE-PD_1210 4575,2398.03 r0 top value=10uH
L5 "XAL1010-682MEB" XAL1010 1826.31,3964.75 r90 top value=6.8uH
L6 "LQM2HPN2R2MG0L" 1008 1382.87,1092.52 r180 bottom value=2.2uH
L7 "MPZ2012S601AT000" MPZ2012 344.49,1668.31 r90 top value="600 ohm"
L8 "MPZ2012S601AT000" MPZ2012 88.58,1353.35 r0 bottom value="600 ohm"
Logo1 "CE Mark" CE_Mark_5mm 969,3989 r0 top
Logo2 "Texas Instruments" TI_Stacked_Overlay_Small 4377.5,4649 r0 top
Logo3 "FCC disclaimer" FCC_disclaimer_stacked 4415.63,4216.43 r0 top
Logo4 "WEEE logo" WEEE_Minimum 515,4036 r0 top
Q1 "IPC50N04S5L5R5ATMA1" PG-TDSON-8-33 2231.31,4147.31 r180 top value=40V
R1 "RC0603JR-070RL" 0603L 2233.15,1375 r270 top value=0
R2 "Resistor" 0402L 3251.5,1637.15 r0 bottom value=15.0k
R3 "Resistor" 0402L 3251.5,1676.15 r0 bottom value=1.0k
R4 "Resistor" 0402L 3251.5,1715.15 r0 bottom value=10.0k
R5 "Resistor" 0402L 3249.5,1855.29 r0 bottom value=10.0k
R6 "RC0603JR-070RL" 0603L 2230,1625.59 r270 top value=0
R7 "Resistor" 0402L 2535.5,445.18 r90 top value=10.0k
R8 "RC0603JR-072K2L" 0603 1757.98,1068.5 r90 top value=2.2k
R9 "RC0603JR-072K2L" 0603 1812.49,1068.5 r90 top value=2.2k
R10 "RC0603JR-071KL" 0603 1758,816.03 r90 top value=1.0k
R11 "RC0603JR-071KL" 0603 1812.47,816.03 r90 top value=1.0k
R12 "RCL12250000Z0EG" 2512_WIDE_VISHAY 1826.31,3894.86 r270 bottom value=0
R13 "RC0603FR-0721KL" 0603 2568.16,4605.65 r180 top value=21.0k
R14 "RMCF0603ZT0R00" 0603L 2599.66,4520.53 r270 top value=0
R15 "RC0603JR-070RL" 0603L 2629.19,4249.86 r270 top value=0
R16 "RC0603FR-0724K9L" 0603L 2568.16,4665.65 r0 top value=24.9k
R17 "RC0603JR-070RL" 0603L 2732.53,4240.02 r270 top value=0
R18 "RC0603FR-07100RL" 0603L 2781.75,4126.83 r270 top value=100
R19 "RC0603FR-0721KL" 0603 2541.31,4509.16 r90 top value=21.0k
R20 "CRCW060349K9FKEA" 0603L 2648.87,4520.53 r90 top value=49.9k
R21 "ERJ-MS4SF4M0U" ERJMS4S 2551.31,4110.65 r180 top value=0.004
R22 "RC0603JR-070RL" 0603L 3086.32,4211.65 r270 top value=0
R23 "RC0603FR-0768KL" 0603 3085,4340 r270 top value=68.0k
R24 "CRCW060311K3FKEA" 0603L 2830.96,4126.83 r90 top value=11.3k
R25 "RC0603JR-070RL" 0603L 2970,4450 r0 top value=0
R26 "RC0603JR-070RL" 0603L 3550,4530 r270 top value=0
R27 "ERJ-3EKF1002V" 0603 3549.39,4336.61 r270 top value=10.0k
R28 "ERJ-3EKF1002V" 0603 3549.5,4134.61 r270 top value=10.0k
R29 "RC0603FR-074K3L" 0603 2995,4340 r90 top value=4.30k
R30 "RC0603JR-070RL" 0603L 2995,4205 r90 top value=0
R31 "RC0805JR-070RL" 0805L 344.49,1791.34 r90 top value=0
R32 "RC0603FR-07249KL" 0603L 359.25,2052.17 r90 top value=249k
R33 "RC0805JR-070RL" 0805L 935.04,3248.03 r90 bottom value=0
R34 "RC0603FR-0766K5L" 0603L 1476.38,885.83 r180 bottom value=66.5k
R35 "RC0603FR-07100KL" 0603L 1579.72,885.83 r180 bottom value=100k
R36 "Resistor" 0402L 821.85,1186.02 r90 bottom value=1.0k
R37 "Resistor" 0402L 1683.07,720.55 r0 bottom value=2.2k
R38 "Resistor" 0402L 1564.96,720.55 r180 bottom value=2.2k
R39 "Resistor" 0402L 1875,1033.46 r90 bottom value=10.0k
R40 "Resistor" 0603L 1279.95,1787.6 r0 top value=4.7
R41 "Resistor" 0402L 605.32,1673.23 r270 bottom value=10k
R42 "Resistor" 0201L 590.55,1870.08 r90 top value=33.2
R43 "Resistor" 0201L 757.87,1943.9 r90 bottom value=33.2
R44 "Resistor" 0201L 1205.71,1943.9 r0 bottom value=33.2
R45 "RC0603FR-07680RL" 0603L 935.04,915.35 r90 top value=680
R46 "Resistor" 0402L 566.93,1444.88 r270 bottom value=10.0k
R47 "Resistor" 0201L 1181.1,1200.79 r270 bottom value=33.2
R48 "ERJ-1GN0R00C" 0201L 1397.64,1481.3 r0 bottom value=0
R49 "ERJ2RKF43R2X" 0402L 585.63,1609.25 r0 bottom value=43.2
R50 "Resistor" 0201 393.7,659.45 r90 top value=10.0k
R51 "Resistor" 0201 1446.85,1505.91 r180 bottom value=10.0k
R52 "Resistor" 0201L 1131.89,787.4 r180 bottom value=33.2
R53 "Resistor" 0201 1131.89,836.61 r0 bottom value=33.2
R54 "Resistor" 0201 236.22,816.93 r0 bottom value=25.5k
R55 "Resistor" 0201 442.91,836.61 r180 bottom value=10.0k
R56 "Resistor" 0201 1338.58,1358.27 r90 bottom value=33.2
R57 "Resistor" 0201 1461.61,1259.84 r180 bottom value=10.0k
R58 "Resistor" 0201 236.22,846.46 r180 bottom value=51.0k
R59 "Resistor" 0402L 566.93,1370.08 r90 bottom value=47.0k
R60 "Resistor" 0402L 826.77,2411.42 r270 bottom value=49.9
R61 "ERJ-2RKF33R0X" 0402L 1427.17,2509.84 r0 top value=33.0
R62 "ERJ-2RKF33R0X" 0402L 1427.17,2460.63 r0 top value=33.0
R63 "ERJ-2RKF33R0X" 0402L 1427.17,2411.42 r0 top value=33.0
R64 "RMCF0603ZT0R00" 0603L 1525.59,2071.85 r270 bottom value=0
R65 "Resistor" 0402L 836.61,2509.84 r0 bottom value=49.9
R66 "Resistor" 0402L 757.87,2613.19 r270 top value=10.0k
R67 "Resistor" 0402L 664.37,2367.13 r270 bottom value=49.9
R68 "CRCW06031K50JNEA" 0603L 492.13,2637.8 r270 bottom value=1.5k
R69 "CRCW0402200KJNED" 0402L 344.49,3248.03 r270 bottom value=200k
R70 "CRCW0402200KJNED" 0402L 344.49,3444.88 r90 bottom value=200k
R71 "CRCW0402680RJNED" 0402L 1018.7,2893.7 r0 top value=680
R72 "Resistor" 0201 1574.8,2214.57 r270 bottom value=10.0k
R73 "RC0603JR-070RL" 0603L 1181.1,2854.33 r180 bottom value=0
R74 "RC0603JR-070RL" 0603L 1279.53,2952.76 r90 bottom value=0
R75 "RC0603JR-070RL" 0603L 1279.53,2706.69 r270 top value=0
R76 "RC0603JR-070RL" 0603L 1387.8,3044.29 r90 bottom value=0
R77 "RC0603JR-070RL" 0603L 1525.59,3051.18 r0 bottom value=0
R78 "RC0603JR-070RL" 0603L 1525.59,2952.76 r0 bottom value=0
R79 "Resistor" 0402L 1240.16,2805.12 r180 bottom value=10.0k
R80 "RC0603JR-070RL" 0603L 1525.59,2864.17 r0 bottom value=0
S1 "PDN" SW_200USP1T1A1M2 2336.29,426.08 r0 top
S2 "I2S SEL" SW_200USP1T1A1M2 1180,3150 r270 top
SH-J1 "SNT-100-BK-G" SNT-100-BK-G 1377.5,1965 r180 top value=1x2
SH-J2 "SNT-100-BK-G" SNT-100-BK-G 1870,1574.8 r90 top value=1x2
SH-J3 "SNT-100-BK-G" SNT-100-BK-G 2082.31,1553.2 r90 top value=1x2
SH-J4 "SNT-100-BK-G" SNT-100-BK-G 2052.5,1267.5 r0 top value=1x2
SH-J5 "SNT-100-BK-G" SNT-100-BK-G 3240,4515 r0 top value=1x2
SH-J6 "SNT-100-BK-G" SNT-100-BK-G 1726.3,2360 r180 top value=1x2
SH-J7 "SNT-100-BK-G" SNT-100-BK-G 1725,2558.9 r180 top value=1x2
SH-J8 "SNT-100-BK-G" SNT-100-BK-G 1722.5,2754.33 r180 top value=1x2
SH-J9 "SNT-100-BK-G" SNT-100-BK-G 1192.5,322.5 r90 top value=1x2
SH-J10 "SNT-100-BK-G" SNT-100-BK-G 1412.5,320 r90 top value=1x2
TP1 "GPIO0_FAULTz" Keystone5003 2457.11,897.5 r90 top
TP2 "GPIO1_Hybrid_Pro" Keystone5003 2457.11,1133.9 r90 top
TP3 "GPIO2_PD_DET" Keystone5003 2034.2,2212.5 r90 top
TP4 "PDN" Keystone5003 2164.2,2211.5 r90 top
TP5 "VOUT" Keystone5003 2357.5,3381.95 r90 top
TP6 "VIN" Keystone5003 1884.34,4560 r90 top
TP7 "FB" Keystone5003 3290,4276.95 r0 top
TP8 "GND" Keystone5003 3800,4315 r0 top
TP9 "GND" Keystone5006 705,3635 r0 top
TP10 "GND" Keystone5006 205,430 r0 top
TP11 "GND" Keystone5006 2055,290 r0 top
TP12 "GND" Keystone5006 5000.38,1808.59 r0 top
TP13 "SCL_XMOS" Keystone5003 600.39,450 r0 top
TP14 "SDA_XMOS" Keystone5003 600.39,250 r0 top
TP15 "MCLK" TP_SM_1MM 679.13,3085.63 r90 top
TP16 "SCLK" Keystone5003 2135.5,2591.24 r0 top
TP17 "LRCLK" Keystone5003 2135.5,2787.67 r0 top
TP18 "SDIN" Keystone5003 2135.5,2394.81 r0 top
TP19 "SCL_AMP" Keystone5003 1413,550 r90 top
TP20 "SDA_AMP" Keystone5003 1195,545 r90 top
TP21 "BST_A+" Keystone5003 4262.5,1558.52 r270 top
TP22 "BST_A-" Keystone5003 4260,1693.52 r90 top
TP23 "BST_B+" Keystone5003 4260,1961.02 r90 top
TP24 "BST_B-" Keystone5003 4260,1831.02 r90 top
U1 "TAS5830DADR" DAD0032A-MFG 3301.36,1740.13 r0 top
U2 "LM5155DSSR" DSS0012B 2668.56,4372.9 r90 top
U3 "TI-TPS7XXXXD8_A" D0008A_M 344.49,2066.93 r0 bottom locked
U4 "TLV62568DBVR" DBV0005A_N 1476.38,984.25 r0 bottom
U5 "TPS736xxDBV" DBV0005A_N 1692.91,1673.23 r270 bottom
U6 "XEF216-512-TQ128-C20A" TQFP-128 984.25,1574.8 r90 bottom locked
U7 "TCA9406DCUR" DCU0008A_N 1771.65,984.25 r0 bottom
U8 "CDCE913PWR" PW0014A_L 1673.23,1328.74 r270 bottom
U9 "SN74AVC2T244" DQM0008A 1456.69,1427.17 r0 bottom
U10 "SN74LVC2G07" DSF0006A 442.91,787.4 r0 bottom
U11 "TPS3897ADRYR" DRY0006A 295.28,787.4 r0 bottom
U12 "OPTO-OUT" FP-FCR684208T_OTJ8-MFG 108.27,2854.33 r180 top
U13 "SN74AVC4T774RSVR" RSV0016A 1328.74,2460.63 r0 top
U14 "PLR237/T10BK" FP-PLR237/T10BK_PTH_9MM70_13MM50-MFG 98.43,2362.2 r270 top
U15 "PCM9211PT" PT0048A_N 688.98,2854.33 r270 top locked
U16 "74LVC2G157DCT" DCT0008A_N 984.25,2165.35 r270 bottom locked
U17 "74LVC2G157DCT" DCT0008A_N 1181.1,2165.35 r270 bottom locked
U18 "SN74LVC1G14" DCK0005A_N 492.13,3006.89 r180 bottom
U19 "74LVC2G157DCT" DCT0008A_N 787.4,2165.35 r270 bottom locked
U20 "74LVC2G157DCT" DCU0008A_L 1673.23,2214.57 r180 bottom
U21 "TI-TCA6408A-QFN_RGT-16" RGT0016A 1377.95,2854.33 r0 bottom
Y1 "ASA-24.000MHZ-L-T" FP-ASA-24.000MHZ-L-T_SMD_2MM0_1MM6-MFG 1367.95,1279.53 r180 bottom
Y2 "ABM10-24.576MHZ-E20-T" XTAL_ABM10 984.25,2726.38 r180 top
ZZ1 "These assemblies are ESD sensitive, ESD precautions shall be observed." AssemblyNote 235,5703 r0 top
ZZ2 "These assemblies must be clean and free from flux and all contaminants. Use of no clean flux is not acceptable." AssemblyNote 235,5594.11 r0 top
ZZ3 "These assemblies must comply with workmanship standards IPC-A-610 Class 2, unless otherwise specified." AssemblyNote 235,5505.56 r0 top

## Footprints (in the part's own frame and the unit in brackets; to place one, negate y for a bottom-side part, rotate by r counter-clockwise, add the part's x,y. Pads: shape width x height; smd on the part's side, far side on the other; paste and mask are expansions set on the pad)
0201 [mm] "Data from Kemet datasheet CC101_COM dated 7/28/11"
  rect 0.46x0.42 smd mask+0.048: 1(-0.33,0) 2(0.33,0)
  body extent -0.31,-0.16 0.31,0.16, height 0.26
0201L [mm] "Data from Kemet datasheet CC101_COM dated 7/28/11"
  rect 0.36x0.32 smd mask+0.048: 1(-0.28,0) 2(0.28,0)
  body extent -0.31,-0.16 0.31,0.16, height 0.26
0402 [mm] "0402 from SM-752 data"
  rect 0.8x0.6 smd: 1(-0.6,0) 2(0.6,0)
  silkscreen extent -1.22,-0.52 1.22,0.52, body extent -0.55,-0.3 0.55,0.3, height 0.6
0402L [mm] "0402 from SM-752 data"
  rect 0.6x0.5 smd: 1(-0.5,0) 2(0.5,0)
  body extent -0.55,-0.3 0.55,0.3, height 0.6
0603 [mm] "0603 from SM-752 data"
  rect 1x0.95 smd: 1(-0.8,0) 2(0.8,0)
  silkscreen extent -1.52,-0.69 1.52,0.69, body extent -0.87,-0.47 0.87,0.47, height 1
0603L [mm] "0603 from SM-752 data"
  rect 0.8x0.85 smd: 1(-0.7,0) 2(0.7,0)
  silkscreen extent -0.07,-0.33 0.07,0.33, body extent -0.87,-0.47 0.87,0.47, height 1
0805L [mm] "0805 from SM-752 data"
  rect 1.1x1.4 smd: 1(-0.75,0) 2(0.75,0)
  body extent -1.1,-0.72 1.1,0.72, height 1.45
1008 [mm] "SMD, Body 2.5x2mm, Height 1.2mm"
  rect 0.8x2.2 smd: 1(-1,0) 2(1,0)
  silkscreen extent -0.4,-1.2 0.4,1.2, body extent -1.35,-1.1 1.35,1.1, height 1.2
1210_280 [mm] "SMD, 2-Leads, Body 3.6x2.8mm, Height 2.8mm"
  rect 1.1x2.2 smd: 1(-1.65,0) 2(1.65,0)
  silkscreen extent -0.84,-1.4 0.84,1.4, body extent -1.8,-1.4 1.8,1.4, height 2.8
2512_WIDE_VISHAY [mm] "Vishay recommended land pattern"
  rect 1.9x7.6 smd: 1(-1.55,0) 2(1.55,0)
  silkscreen extent -0.3,-3.32 0.3,3.35, body extent -1.7,-3.25 1.7,3.25, height 0.9
"APM_RM3X8MM 2701" [mm] "Screw, Dia 6.7mm, Length 8mm, TH"
  round 5.5 hole 3.6: ""(0,0)
  silkscreen extent -3.35,-3.35 3.35,3.35, body extent -3.32,-3.34 3.35,3.34, height 2.38
AssemblyNote [mil] "Assembly Note"
CE_Mark_5mm [mil] "Minimum text height for CE Mark"
  silkscreen extent -138,-98 138,98
CONN_1040 [mil] "Test Point, PC  test point Terminal"
  round 75 hole 52: 1(0,0)
  body extent -55,-12 55,13, height 276
D0008A_M [mm] "SOIC, 8-Leads, Body 4.9x3.9mm, Pitch 1.27mm, IPC Low Density"
  oval 1.65x0.65 smd: 1(-2.825,1.905) 2(-2.825,0.635) 3(-2.825,-0.635) 4(-2.825,-1.905) 5(2.825,-1.905) 6(2.825,-0.635) 7(2.825,0.635) 8(2.825,1.905)
  silkscreen extent -3.3,-2.5 0.9,2.5, body extent -3,-2.45 3,2.45, height 1.63
DAD0032A-MFG [mm] "Recommended Land Pattern"
  rrect22% 1.5x0.45 smd paste+0 mask+0: 1(-3.75,4.875) 2(-3.75,4.225) 3(-3.75,3.575) 4(-3.75,2.925) 5(-3.75,2.275) 6(-3.75,1.625) 7(-3.75,0.975) 8(-3.75,0.325) 9(-3.75,-0.325) 10(-3.75,-0.975) 11(-3.75,-1.625) 12(-3.75,-2.275) 13(-3.75,-2.925) 14(-3.75,-3.575) 15(-3.75,-4.225) 16(-3.75,-4.875) 17(3.75,-4.875) 18(3.75,-4.225) 19(3.75,-3.575) 20(3.75,-2.925) 21(3.75,-2.275) 22(3.75,-1.625) 23(3.75,-0.975) 24(3.75,-0.325) 25(3.75,0.325) 26(3.75,0.975) 27(3.75,1.625) 28(3.75,2.275) 29(3.75,2.925) 30(3.75,3.575) 31(3.75,4.225) 32(3.75,4.875)
  silkscreen extent -5.17,-5.55 3.1,5.55, body extent -4.6,-5.65 4.6,5.65, height 0.25
DBV0005A_N [mm] "SOT23, 5-Leads, Body 2.9x1.6mm, Pitch 0.95mm, Lead Span 2.8mm, IPC Medium Density"
  rrect17% 1x0.6 smd: 1(-1.375,0.95) 2(-1.375,0) 3(-1.375,-0.95) 4(1.375,-0.95) 5(1.375,0.95)
  silkscreen extent -0.25,-1.55 0.25,1.55, body extent -1.42,-1.46 1.42,1.46, height 1.09
DCK0005A_N [mm] "SOT353, 5-Leads, Body 2x1.3mm, Pitch 0.65mm, Lead Span 2.1mm, IPC Medium Density"
  rrect25% 0.85x0.4 smd: 1(-1.125,0.65) 2(-1.125,0) 3(-1.125,-0.65) 4(1.125,-0.65) 5(1.125,0.65)
  silkscreen extent -1.48,-1.02 0.55,1.1, body extent -1.14,-1 1.14,1, height 0.95
DCT0008A_N [mm] "TSOP, 8-Leads, Body 3x2.8mm, Pitch 0.65mm, IPC Medium Density"
  oval 1.05x0.4 smd: 1(-1.975,0.975) 2(-1.975,0.325) 3(-1.975,-0.325) 4(-1.975,-0.975) 5(1.975,-0.975) 6(1.975,-0.325) 7(1.975,0.325) 8(1.975,0.975)
  silkscreen extent -2.32,-1.57 0.6,1.58, body extent -2.01,-1.47 2.01,1.48, height 1.3
DCU0008A_L [mm] "TSSOP, 8-Leads, Body 2x2.3mm, Pitch 0.5mm, IPC High Density"
  oval 0.6x0.25 smd: 1(-1.5,0.75) 2(-1.5,0.25) 3(-1.5,-0.25) 4(-1.5,-0.75) 5(1.5,-0.75) 6(1.5,-0.25) 7(1.5,0.25) 8(1.5,0.75)
  silkscreen extent -1.05,-1.05 0.38,1.05, body extent -1.56,-1 1.56,1, height 0.9
DCU0008A_N [mm] "TSSOP, 8-Leads, Body 2x2.3mm, Pitch 0.5mm, IPC Medium Density"
  oval 0.8x0.3 smd: 1(-1.6,0.75) 2(-1.6,0.25) 3(-1.6,-0.25) 4(-1.6,-0.75) 5(1.6,-0.75) 6(1.6,-0.25) 7(1.6,0.25) 8(1.6,0.75)
  silkscreen extent -1.05,-1.05 0.38,1.05, body extent -1.56,-1 1.56,1, height 0.9
DQM0008A [mm] "TI"
  rrect50% 0.7x0.2 smd: 1(-0.45,0.6) 2(-0.45,0.2) 3(-0.45,-0.2) 4(-0.45,-0.6) 5(0.45,-0.6) 6(0.45,-0.2) 7(0.45,0.2) 8(0.45,0.6)
  silkscreen extent -0.72,-1.02 0.72,1.02, body extent -0.6,-0.9 0.6,0.9, height 0.5
DRY0006A [mm] "USON-6"
  rrect67% 0.45x0.3 smd paste-0.05 mask-0.05: 1(-0.275,0.5)
  rrect67% 0.4x0.3 smd paste-0.05 mask-0.05: 2(-0.3,0) 3(-0.3,-0.5) 4(0.3,-0.5) 5(0.3,0) 6(0.3,0.5)
  body extent -0.5,-0.72 0.5,0.72, height 0.58
DSF0006A [mm] "TI recommended land pattern"
  rrect59% 0.6x0.17 smd mask+0.045: 1(-0.4,0.35) 2(-0.4,0) 3(-0.4,-0.35) 4(0.4,-0.35) 5(0.4,0) 6(0.4,0.35)
  silkscreen extent -0.6,-0.63 0.6,0.63, body extent -0.5,-0.5 0.5,0.5, height 0.48
DSS0012B [mm] "WSON-10"
  rrect40% 0.5x0.25 smd: 1(-0.95,1.25) 2(-0.95,0.75) 3(-0.95,0.25) 4(-0.95,-0.25) 5(-0.95,-0.75) 6(-0.95,-1.25) 7(0.95,-1.25) 8(0.95,-0.75) 9(0.95,-0.25) 10(0.95,0.25) 11(0.95,0.75) 12(0.95,1.25)
  rrect11% 1x2.65 smd paste-0.5: 13(0,0)
  body extent -1,-1.5 1,1.5, height 0.81
ERJMS4S [mm] "SMD, 2-Leads, Body 6.4x3.2mm"
  rrect4% 2.7x3.4 smd: 1(-2.35,0) 2(2.35,0)
  silkscreen extent -0.7,-1.55 0.7,1.55, body extent -3.2,-1.6 3.2,1.6, height 1.35
FCC_disclaimer_stacked [mil]
Fiducial6.4-20 [mil]
  round 25 smd mask+26.87: 1(0,0)
  Top Layer keep-out circle w46.37: c0,0 r19.68
FP-ASA-24.000MHZ-L-T_SMD_2MM0_1MM6-MFG [mm]
  rrect15% 0.75x0.65 smd paste+0 mask+0: 1(-0.65,-0.5) 2(0.65,-0.5) 3(0.65,0.5) 4(-0.65,0.5)
  silkscreen extent -1.45,-1.52 1.45,0.85, body extent -1,-0.8 1,0.8, height 0.8
FP-CGA4J3X7R1H684M125AB_0805-MFG [mm]
  rrect13% 0.8x1.05 smd paste+0 mask+0: 1(-0.925,0) 2(0.925,0)
  body extent -1.43,-0.82 1.43,0.82, height 0.25
FP-FCR684208T_OTJ8-MFG [mm]
  rrect8% 1.3x1.3 hole 0.8 paste-1000 mask+0: 1(-4.25,2.54)
  round 1.3 hole 0.8 paste-1000 mask+0: 2(-4.25,0) 3(-4.25,-2.54)
  round 1.7 hole 1.1 paste-1000 mask+0: 4(-1.65,2.54) 5(-1.65,-2.54)
  round 1.7 hole 1.7 unplated paste-1000 mask+0: ""(0.85,2.8) ""(0.85,-2.8)
  silkscreen extent -7.45,-4.95 6.85,4.95, body extent -6.95,-5.05 6.95,5.05, height 0.25
FP-PLR237/T10BK_PTH_9MM70_13MM50-MFG [mm] "EVERLIGHT"
  rrect8% 1.3x1.3 hole 0.8 paste-1000 mask+0: 1(-2.54,4.36)
  round 1.3 hole 0.8 paste-1000 mask+0: 2(0,4.36) 3(2.54,4.36)
  round 1.7 hole 1.1 paste-1000 mask+0: 4(-2.54,1.74) 5(2.54,1.74)
  silkscreen extent -5.6,-6.9 5,6.9, body extent -5.1,-7 5.1,7, height 0.25
HARWIN_S1911-46R [mm] "HARWIN"
  rect 2.48x3 smd mask+0.102: 1(-2.69,0) 2(2.69,0)
  silkscreen extent -0.5,-1.5 0.5,1.5, body extent -3.42,-1.25 3.43,1.26, height 0.99
HSINK_ATS078036036-TI1OP-519-C1-R3 [mm] "TH, 2-Leads, Body 78x36mm, Height 35.6mm"
  round 3.5 hole 3: 1(-18.4,0) 2(18.4,0)
  body extent -39.19,-18.2 39.19,18.2, height 35.6
HXB_JA0 [mm] "SMD, 2-Leads, Dia 10mm"
  rect 4.4x2.2 smd: 1(-4.45,0) 2(4.45,0)
  silkscreen extent -5.25,-5.25 5.25,5.25, body extent -5.25,-5.25 5.25,5.25, height 10.31
JST_B2PS-VH [mm] "JST Sales America Inc"
  rect 2.4x2.4 hole 1.778: 1(0,1.98)
  round 2.4 hole 1.778: 2(0,-1.98)
  silkscreen extent 2,-3.93 14.9,3.93, body extent -0.57,-3.93 14.9,3.93, height 8.52
Keystone5003 [mil] "For Keystone 500x miniature loop terminals"
  round 80 hole 40: 1(0,0)
  silkscreen extent -52,-52 52,52, body extent -49,-49 49,49, height 182
Keystone5006 [mil] "Keystone Compact loops"
  round 87 hole 63: 1(0,0)
  silkscreen extent -70,-70 70,70, body extent -63,-63 62,63, height 225
Keystone_7006 [mm] "KEYSTONE"
  round 8.5 hole 3.658: 1(0,0)
  silkscreen extent -4.8,-4.8 4.8,4.8, body extent -5.68,-5.69 5.7,5.69, height 26.47
Keystone_7007 [mm] "KEYSTONE"
  round 8.5 hole 3.658: 1(0,0)
  silkscreen extent -4.8,-4.8 4.8,4.8, body extent -5.71,-5.66 5.67,5.72, height 26.48
Keystone_24434 [mil] "Keystone"
  body extent -114,-98 114,98, height 472
LTST-C170TBKT_Blue [mm] "LITE-ON"
  rect 1.2x1.2 smd: 1(-1.05,0) 2(1.05,0)
  silkscreen extent -1.6,-1 2.2,1, body extent -1.05,-0.67 1.05,0.67, height 1.2
Molex_0475890001 [mm] "Molex"
  rrect25% 0.4x1.35 smd: 1(-1.3,4.125) 2(-0.65,4.125) 3(0,4.125) 4(0.65,4.125) 5(1.3,4.125)
  oval 1.05x1.3 hole 0.7 slot 0.85 at 90 deg: 6(2.225,4.45) 11(-2.225,4.45)
  oval 0.8x2 hole 0.6 slot 1.3 at 90 deg: 7(4.175,1.45) 10(-4.175,1.45)
  rrect6% 1.8x2 smd: 8(1.15,1.45) 9(-1.15,1.45)
  Top Layer region: -4.175,0.45 -4.175,2.45 -2.6,2.45 -2.6,0.45
  Top Layer region: 2.6,0.45 2.6,2.45 4.175,2.45 4.175,0.45
  silkscreen extent -3.75,2.85 3.75,4.3, body extent -4.32,-1.3 4.33,4.59, height 2.81
MPZ2012 [mm] "TDK"
  rect 0.8x1.2 smd: 1(-0.9,0) 2(0.9,0)
  body extent -1.1,-0.72 1.1,0.72, height 1.05
PBC03SAAN [mm] "Sullins 100mil, 1x3, 230 mil above insulator"
  rect 1.65x1.65 hole 1.016: 1(-2.54,0)
  round 1.65 hole 1.016: 2(0,0) 3(2.54,0)
  silkscreen extent -3.81,-1.27 3.81,1.27, body extent -3.81,-1.27 3.81,1.27, height 8.38
PG-TDSON-8-33 [mm] "Infineon recommended land pattern"
  rrect29% 1.65x0.7 smd paste-1 mask-0.05: 1(-2.995,1.905) 2(-2.995,0.635) 3(-2.995,-0.635) 4(-2.995,-1.905) 5(2.995,-1.905) 6(2.995,-0.635) 7(2.995,0.635) 8(2.995,1.905)
  Top Layer region: -3.82,-0.565 -3.82,1.835 -3.816,1.854 -3.805,1.87 -3.789,1.881 -3.77,1.885 -3.77,1.885 -2.22,1.885 -2.201,1.881 -2.185,1.87 -2.174,1.854 -2.17,1.835 -2.17,1.835 -2.17,-0.565 -2.174,-0.584 -2.185,-0.6 -2.201,-0.611 -2.22,-0.615 -2.22,-0.615 -3.77,-0.615 -3.789,-0.611 -3.805,-0.6 -3.816,-0.584 -3.82,-0.565
  Top Layer region: -1.18,-2.155 -1.18,2.155 -1.172,2.193 -1.151,2.226 -1.118,2.247 -1.08,2.255 -1.08,2.255 3.72,2.255 3.758,2.247 3.791,2.226 3.812,2.193 3.82,2.155 3.82,2.155 3.82,-2.155 3.812,-2.193 3.791,-2.226 3.758,-2.247 3.72,-2.255 3.72,-2.255 -1.08,-2.255 -1.118,-2.247 -1.151,-2.226 -1.172,-2.193 -1.18,-2.155
  body extent -3.22,-2.71 3.22,2.7, height 1.01
PT0048A_N [mm] "Thin QFP, 48-Leads, Body 7x7mm, Pitch 0.5mm, IPC Medium Density"
  oval 1.45x0.3 smd: 1(-4.225,2.75) 2(-4.225,2.25) 3(-4.225,1.75) 4(-4.225,1.25) 5(-4.225,0.75) 6(-4.225,0.25) 7(-4.225,-0.25) 8(-4.225,-0.75) 9(-4.225,-1.25) 10(-4.225,-1.75) 11(-4.225,-2.25) 12(-4.225,-2.75) 25(4.225,-2.75) 26(4.225,-2.25) 27(4.225,-1.75) 28(4.225,-1.25) 29(4.225,-0.75) 30(4.225,-0.25) 31(4.225,0.25) 32(4.225,0.75) 33(4.225,1.25) 34(4.225,1.75) 35(4.225,2.25) 36(4.225,2.75)
  oval 0.3x1.45 smd: 13(-2.75,-4.225) 14(-2.25,-4.225) 15(-1.75,-4.225) 16(-1.25,-4.225) 17(-0.75,-4.225) 18(-0.25,-4.225) 19(0.25,-4.225) 20(0.75,-4.225) 21(1.25,-4.225) 22(1.75,-4.225) 23(2.25,-4.225) 24(2.75,-4.225) 37(2.75,4.225) 38(2.25,4.225) 39(1.75,4.225) 40(1.25,4.225) 41(0.75,4.225) 42(0.25,4.225) 43(-0.25,4.225) 44(-0.75,4.225) 45(-1.25,4.225) 46(-1.75,4.225) 47(-2.25,4.225) 48(-2.75,4.225)
  silkscreen extent -4.35,-3.1 3.1,3.58, body extent -4.51,-4.51 4.51,4.51, height 1.5
PW0014A_L [mm] "TSOP, 14-Leads, Body 5x4.4mm, Pitch 0.65mm, IPC High Density"
  oval 1.2x0.4 smd: 1(-2.85,1.95) 2(-2.85,1.3) 3(-2.85,0.65) 4(-2.85,0) 5(-2.85,-0.65) 6(-2.85,-1.3) 7(-2.85,-1.95) 8(2.85,-1.95) 9(2.85,-1.3) 10(2.85,-0.65) 11(2.85,0) 12(2.85,0.65) 13(2.85,1.3) 14(2.85,1.95)
  silkscreen extent -3.2,-2.55 1.85,2.55, body extent -3.21,-2.5 3.21,2.5, height 1
RGT0016A [mm] "QFN, 16-Leads, Body 3x3mm, Pitch 0.5mm, Thermal Pad 1.45x1.45mm, TI Recommended"
  rrect42% 0.6x0.24 smd: 1(-1.4,0.75) 2(-1.4,0.25) 3(-1.4,-0.25) 4(-1.4,-0.75) 9(1.4,-0.75) 10(1.4,-0.25) 11(1.4,0.25) 12(1.4,0.75)
  rrect42% 0.24x0.6 smd: 5(-0.75,-1.4) 6(-0.25,-1.4) 7(0.25,-1.4) 8(0.75,-1.4) 13(0.75,1.4) 14(0.25,1.4) 15(-0.25,1.4) 16(-0.75,1.4)
  rrect7% 1.34x1.34 on Bottom Paste: 17(0,0)
  rrect7% 1.45x1.45 smd paste-0.725: 17(0,0)
  silkscreen extent -1.72,-1.73 1.72,1.73, body extent -1.5,-1.5 1.5,1.5, height 1
RSV0016A [mm] "QFN, 16-Leads, Body 1.8x2.6mm, Pitch 0.4mm, TI Recommended"
  rect 0.7x0.2 smd: 1(-0.75,0.6)
  rect 0.6x0.2 smd: 2(-0.8,0.2) 3(-0.8,-0.2) 4(-0.8,-0.6) 9(0.8,-0.6) 10(0.8,-0.2) 11(0.8,0.2) 12(0.8,0.6)
  rect 0.2x0.6 smd: 5(-0.6,-1.2) 6(-0.2,-1.2) 7(0.2,-1.2) 8(0.6,-1.2) 13(0.6,1.2) 14(0.2,1.2) 15(-0.2,1.2) 16(-0.6,1.2)
  silkscreen extent -1.08,-1.33 1.08,1.45, body extent -0.92,-1.32 0.92,1.33, height 0.56
SM_RADIAL_10BMM [mm] "Nichicon 10x10"
  rect 4x2.5 smd: 1(-4,0) 2(4,0)
  silkscreen extent -5.25,-5.25 5.25,5.25, body extent -5.25,-5.25 5.25,5.25, height 10.5
SM_RADIAL_B [mm] "4 x 5.8mm:  Panasonic B"
  rect 2.5x1.6 smd: 1(-1.75,0) 2(1.75,0)
  silkscreen extent -2.24,-2.25 2.25,2.25, body extent -2.25,-2.25 2.25,2.25, height 6.1
SNT-100-BK-G [mil] "Samtec STEP model"
  round 1 on Mech3: 0(0,0)
  body extent -100,-50 100,50, height 344
SOT1289 [mm] "CFP15, Nexperia recommended land pattern"
  rect 1.6x1.44 smd paste-0.8 mask+0.1: 1(-1.065,2.78) 2(1.065,2.78)
  rect 3.8x4.96 smd paste-2.48 mask+0.1: 3(0,-1.02)
  body extent -2.15,-3.25 2.15,3.25, height 0.79
SULLINS_LPPB061NGCN-RC [mm] "SULLINS"
  rect 1.05x1.05 hole 0.61: 1(3.175,2.54)
  round 1.05 hole 0.61: 2(1.905,2.54) 3(0.635,2.54) 4(-0.635,2.54) 5(-1.905,2.54) 6(-3.175,2.54)
  silkscreen extent -4,-2.37 4.03,2, body extent -4,-2.36 4,2.59, height 2.16
Sullins_PBC02SAAN [mm] "Sullins 100mil, 1x2, 230 mil above insulator"
  rect 1.65x1.65 hole 1.016: 1(0,1.27)
  round 1.65 hole 1.016: 2(0,-1.27)
  silkscreen extent -1.37,-2.54 1.27,3.1, body extent -1.27,-2.54 1.27,2.54, height 8.38
SW_200USP1T1A1M2 [mm] "TH, 5-Leads, Body 7x4.5mm, Pitch 2.54mm"
  rect 1.4x1.4 hole 0.9: 1(-1.27,2.54)
  round 1.4 hole 0.9: 3(-1.27,-2.54) 4(1.27,2.54) 5(1.27,0) 6(1.27,-2.54)
  silkscreen extent -2.7,-3.63 2.38,3.63, body extent -2.37,-3.62 2.38,3.63, height 11.13
Switchcraft_35RASM [mil] "Switchcraft"
  rect 83x92 smd: 1(-159.5,142.5) 2(159.5,67.5)
  rect 83x111 smd: 3(-159.5,-224.5)
  rect 83x84 smd: 4(159.5,173.5)
  rect 111x107 smd: 5(29,-390.5)
  rect 0x0 hole 63 unplated: MH1(0,98.5) MH2(0,-177.5)
  silkscreen extent -161,-339 121,340, body extent -120,-339 120,340, height 202
TI_Stacked_Overlay_Small [mil]
  silkscreen extent -418,-98 418,98
TP_SM_1MM [mm] "1mm Test Point, SMT"
  round 1 smd paste-0.5: 1(0,0)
